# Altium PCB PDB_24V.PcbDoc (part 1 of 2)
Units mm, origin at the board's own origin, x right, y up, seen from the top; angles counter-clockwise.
Board outline 185 x 160 mm, 4 copper layers (Top Layer, Int1 (GND), Int2 (GND), Bottom Layer), stack 1.636 mm thick; 170 components, 90 nets, 598 pads, 1109 vias.
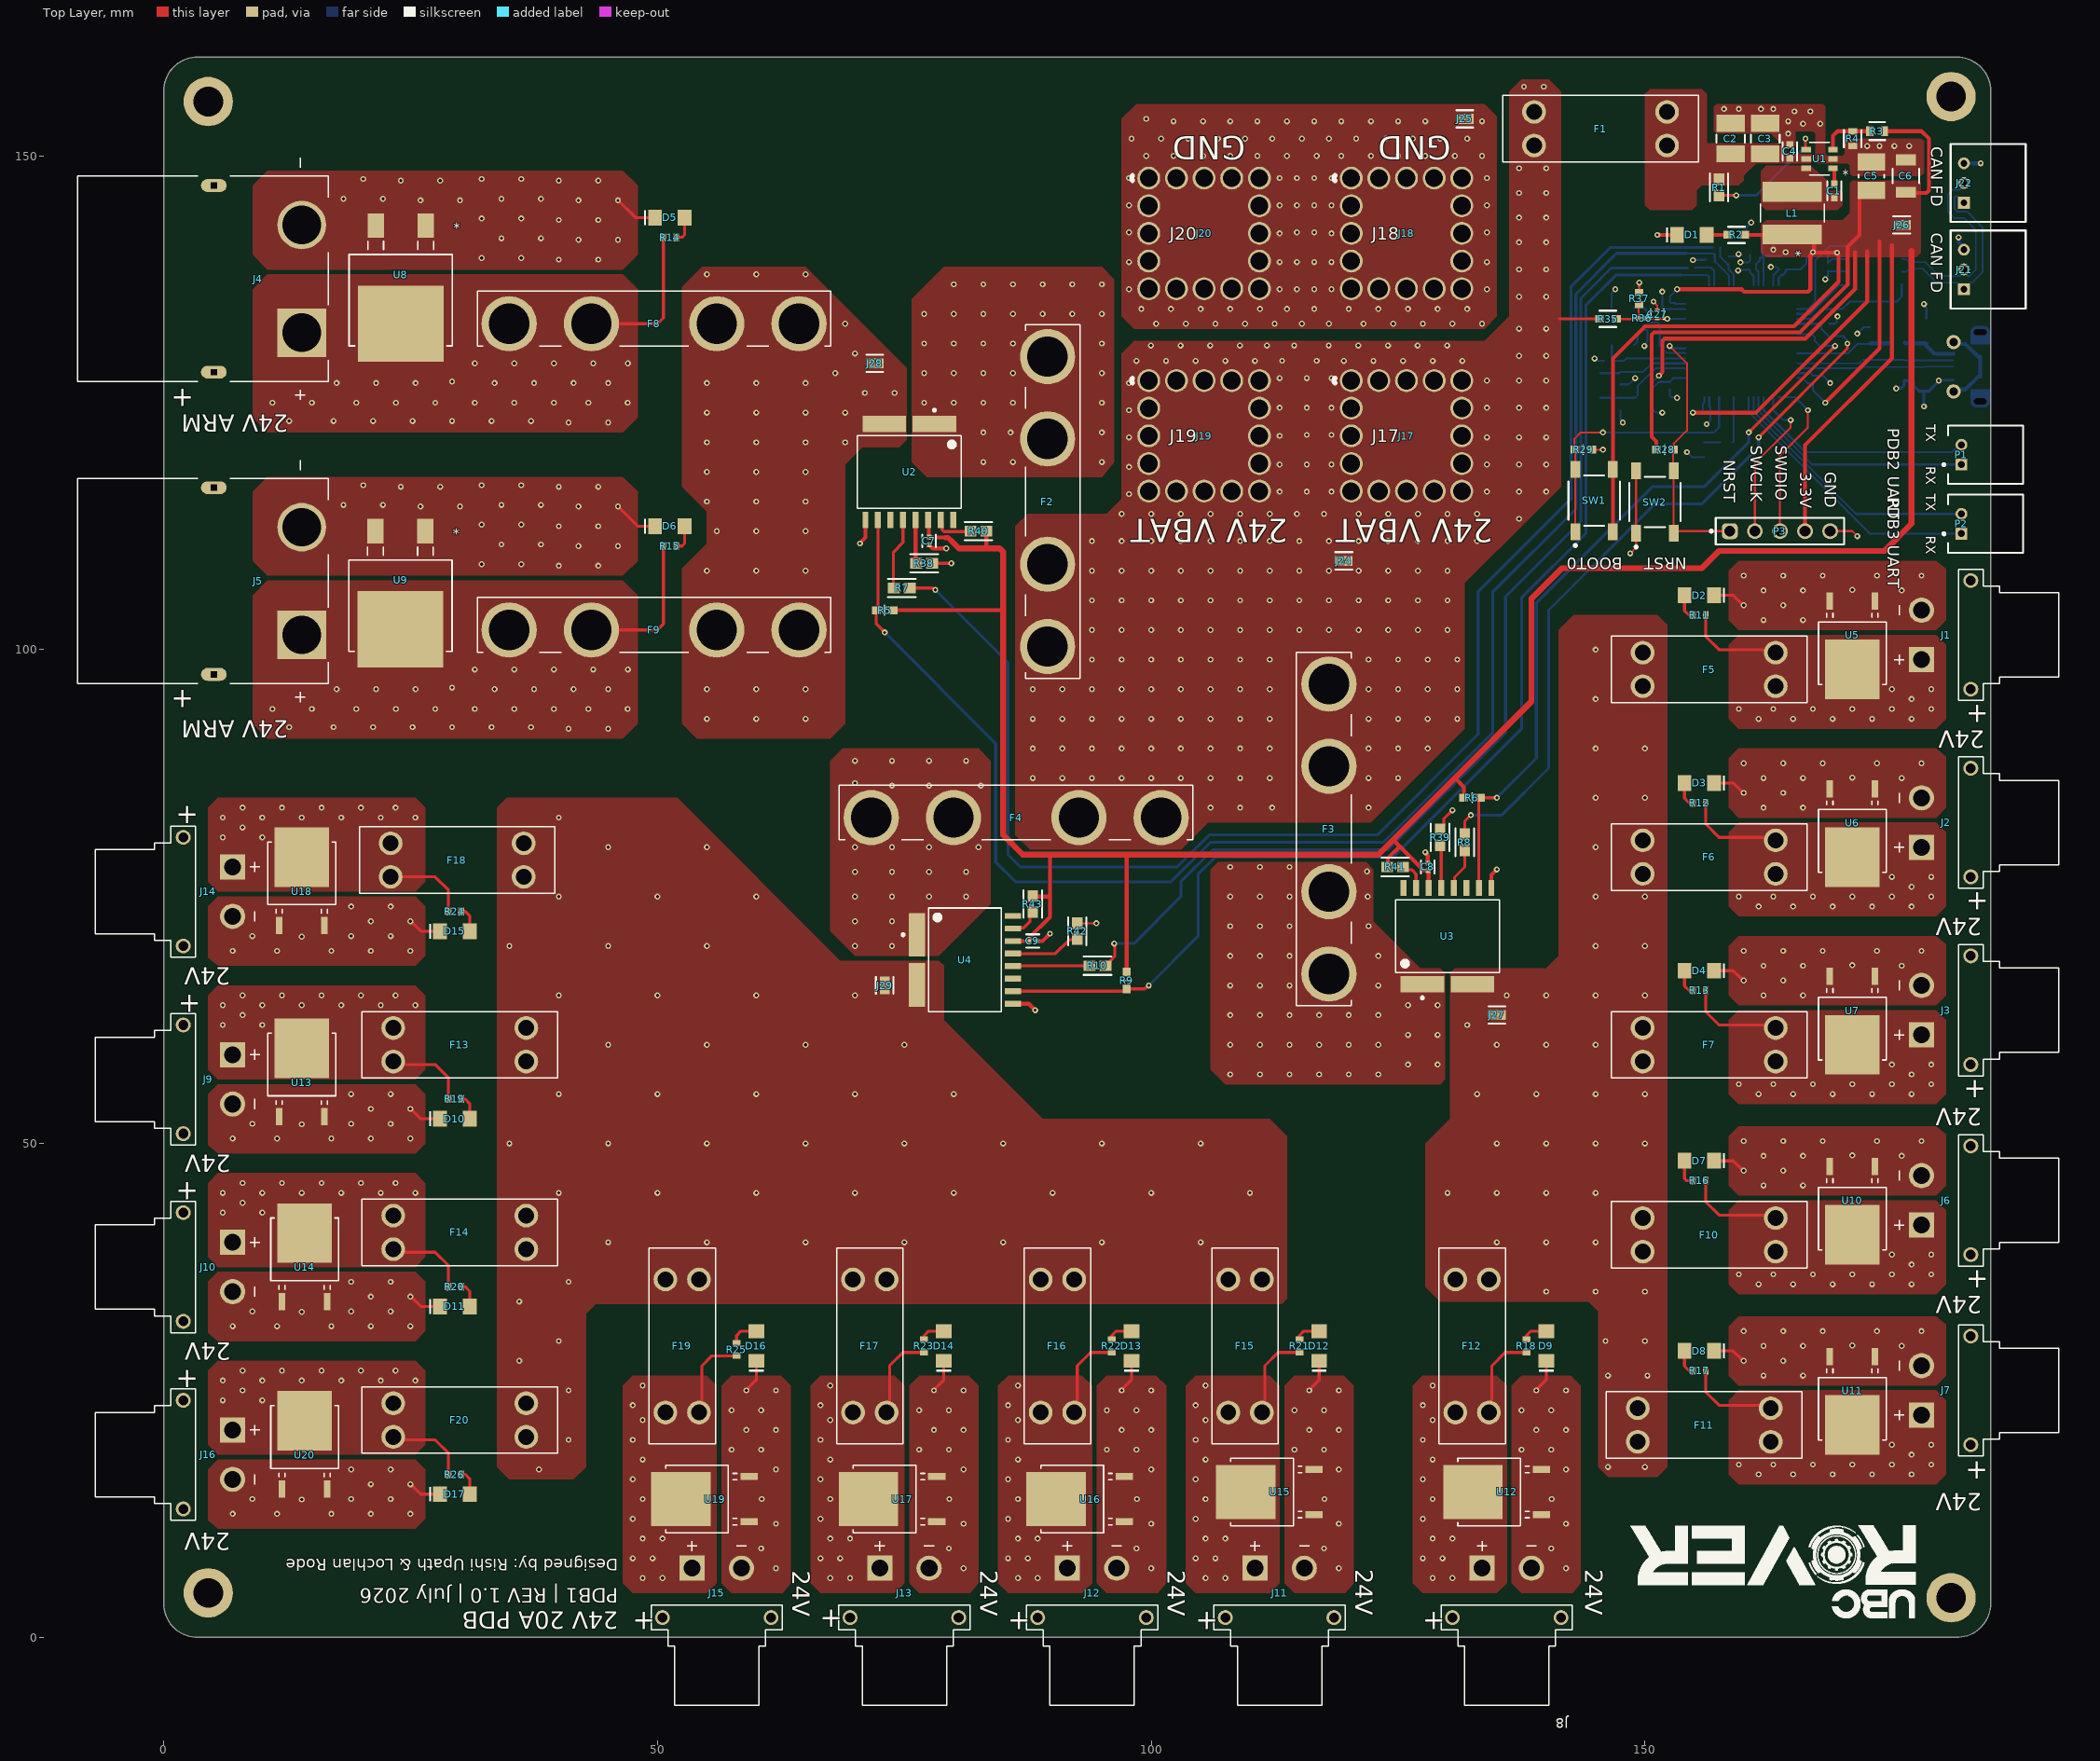
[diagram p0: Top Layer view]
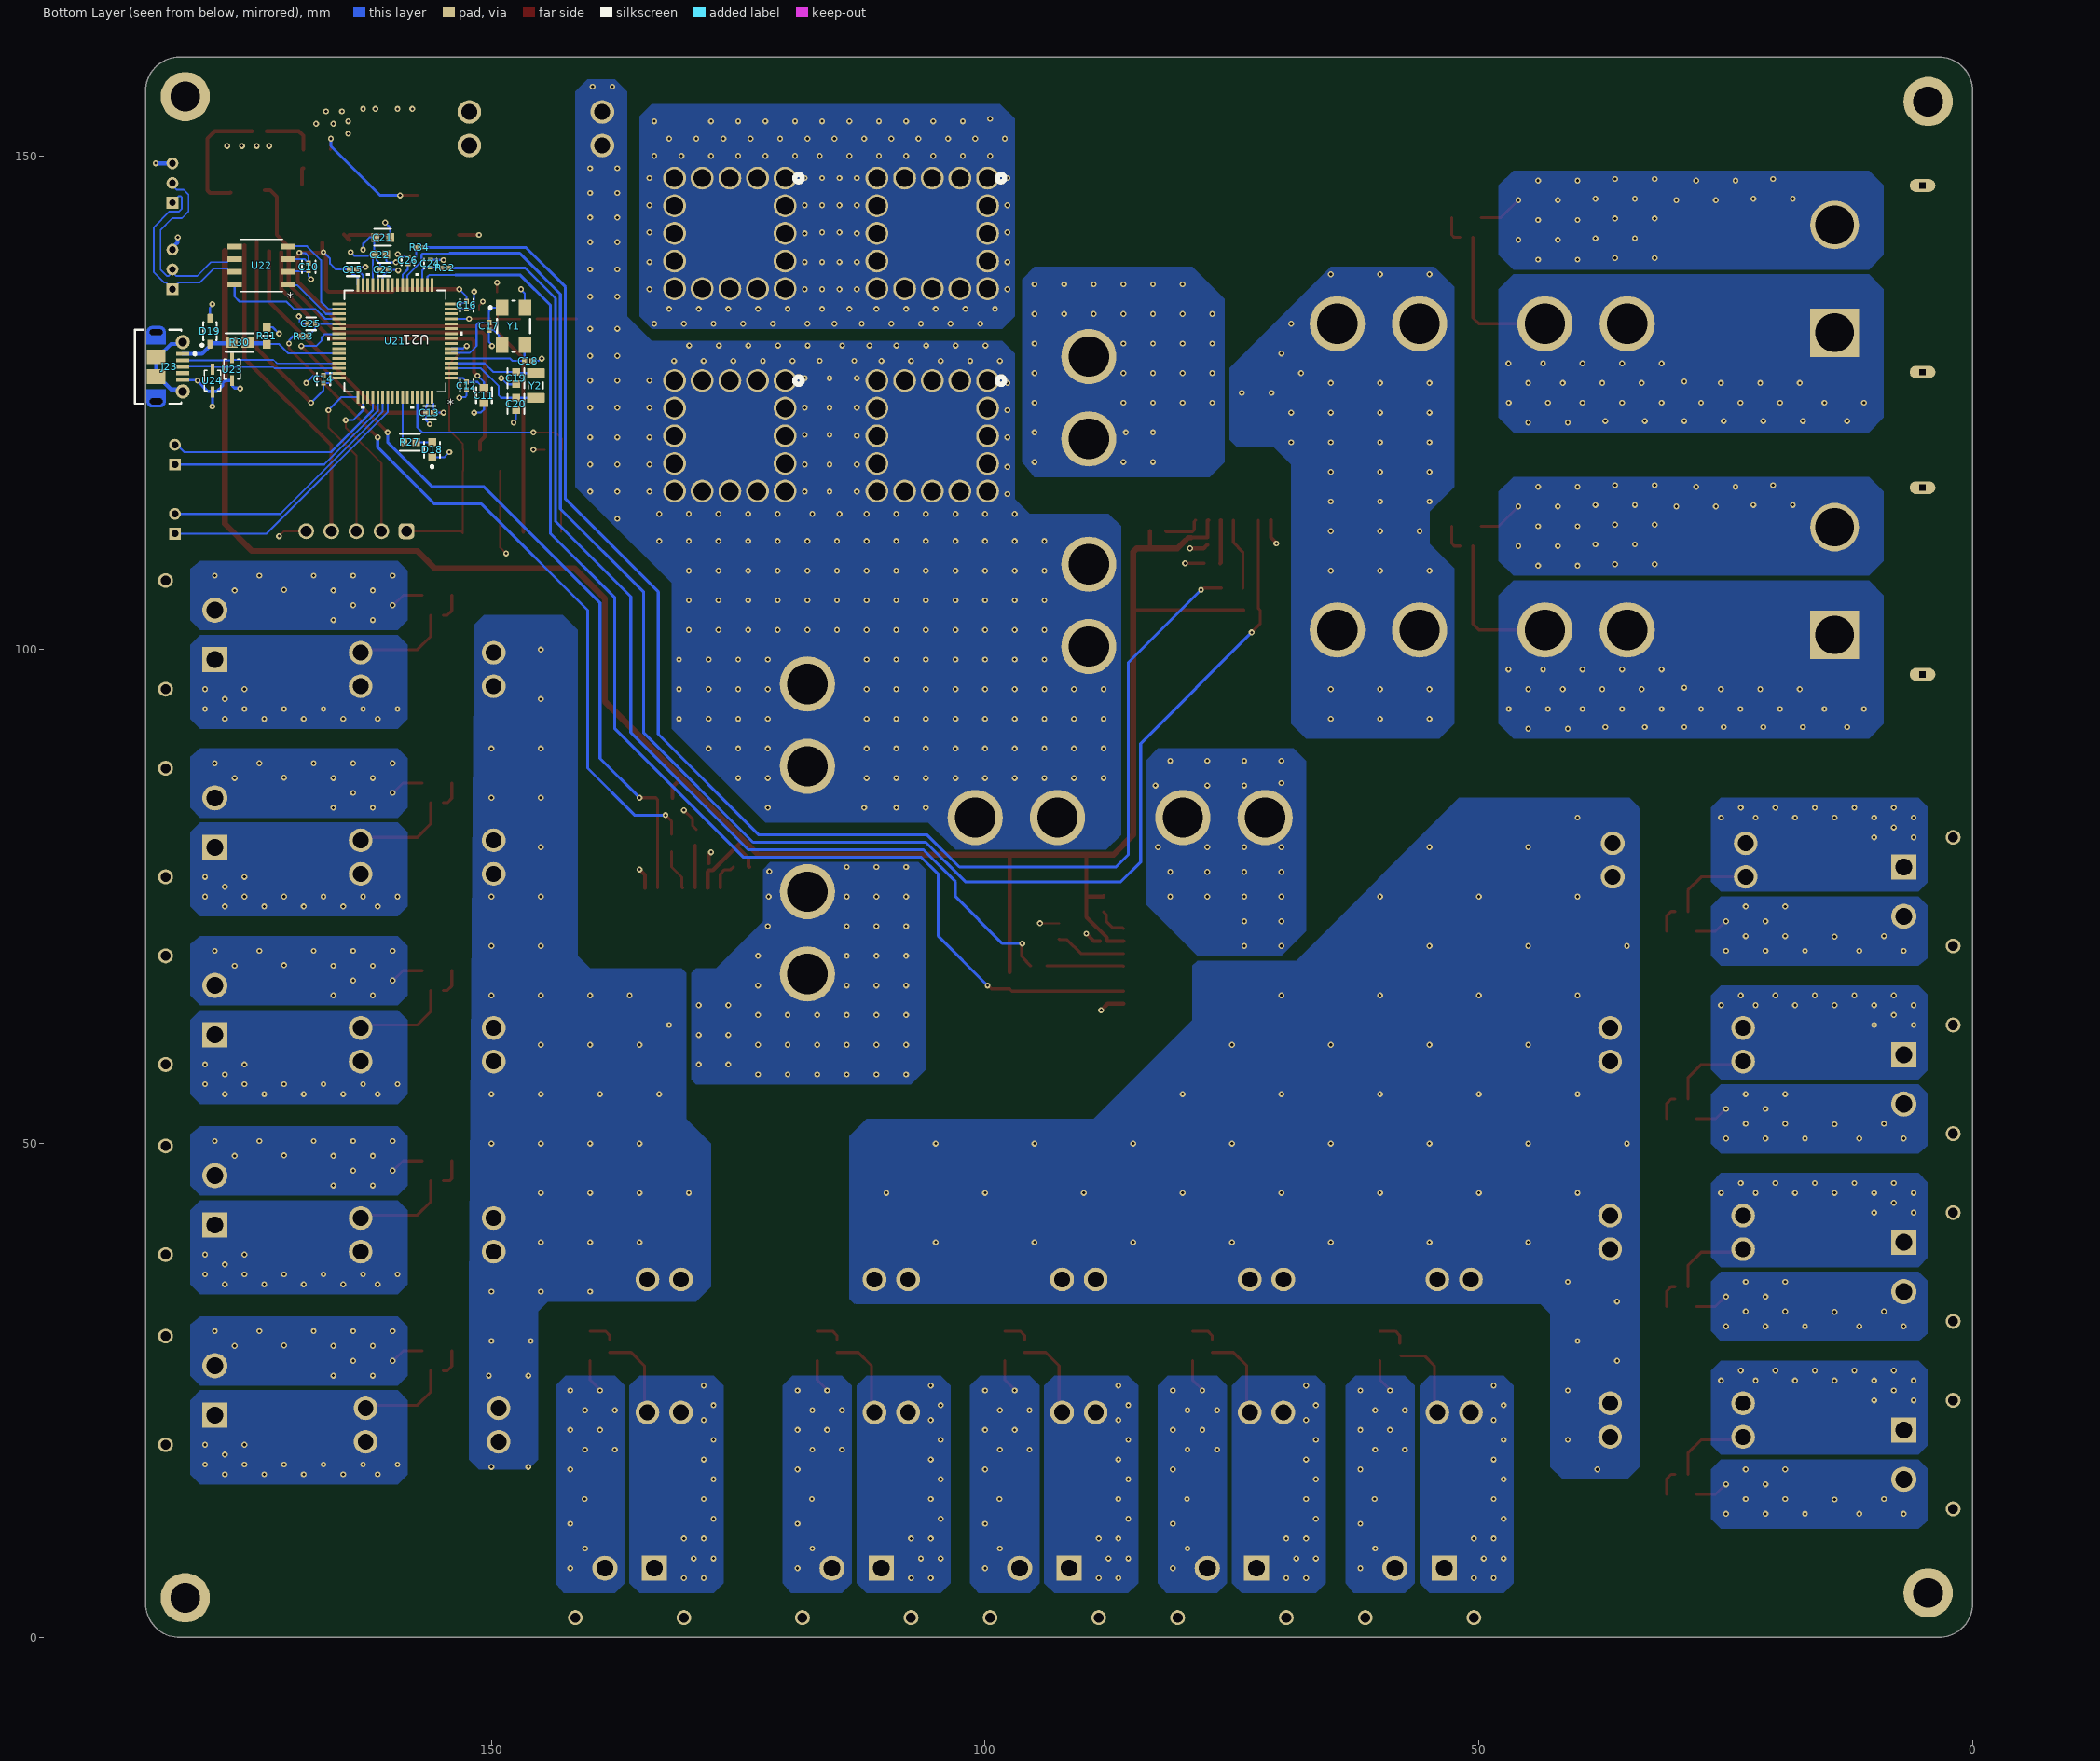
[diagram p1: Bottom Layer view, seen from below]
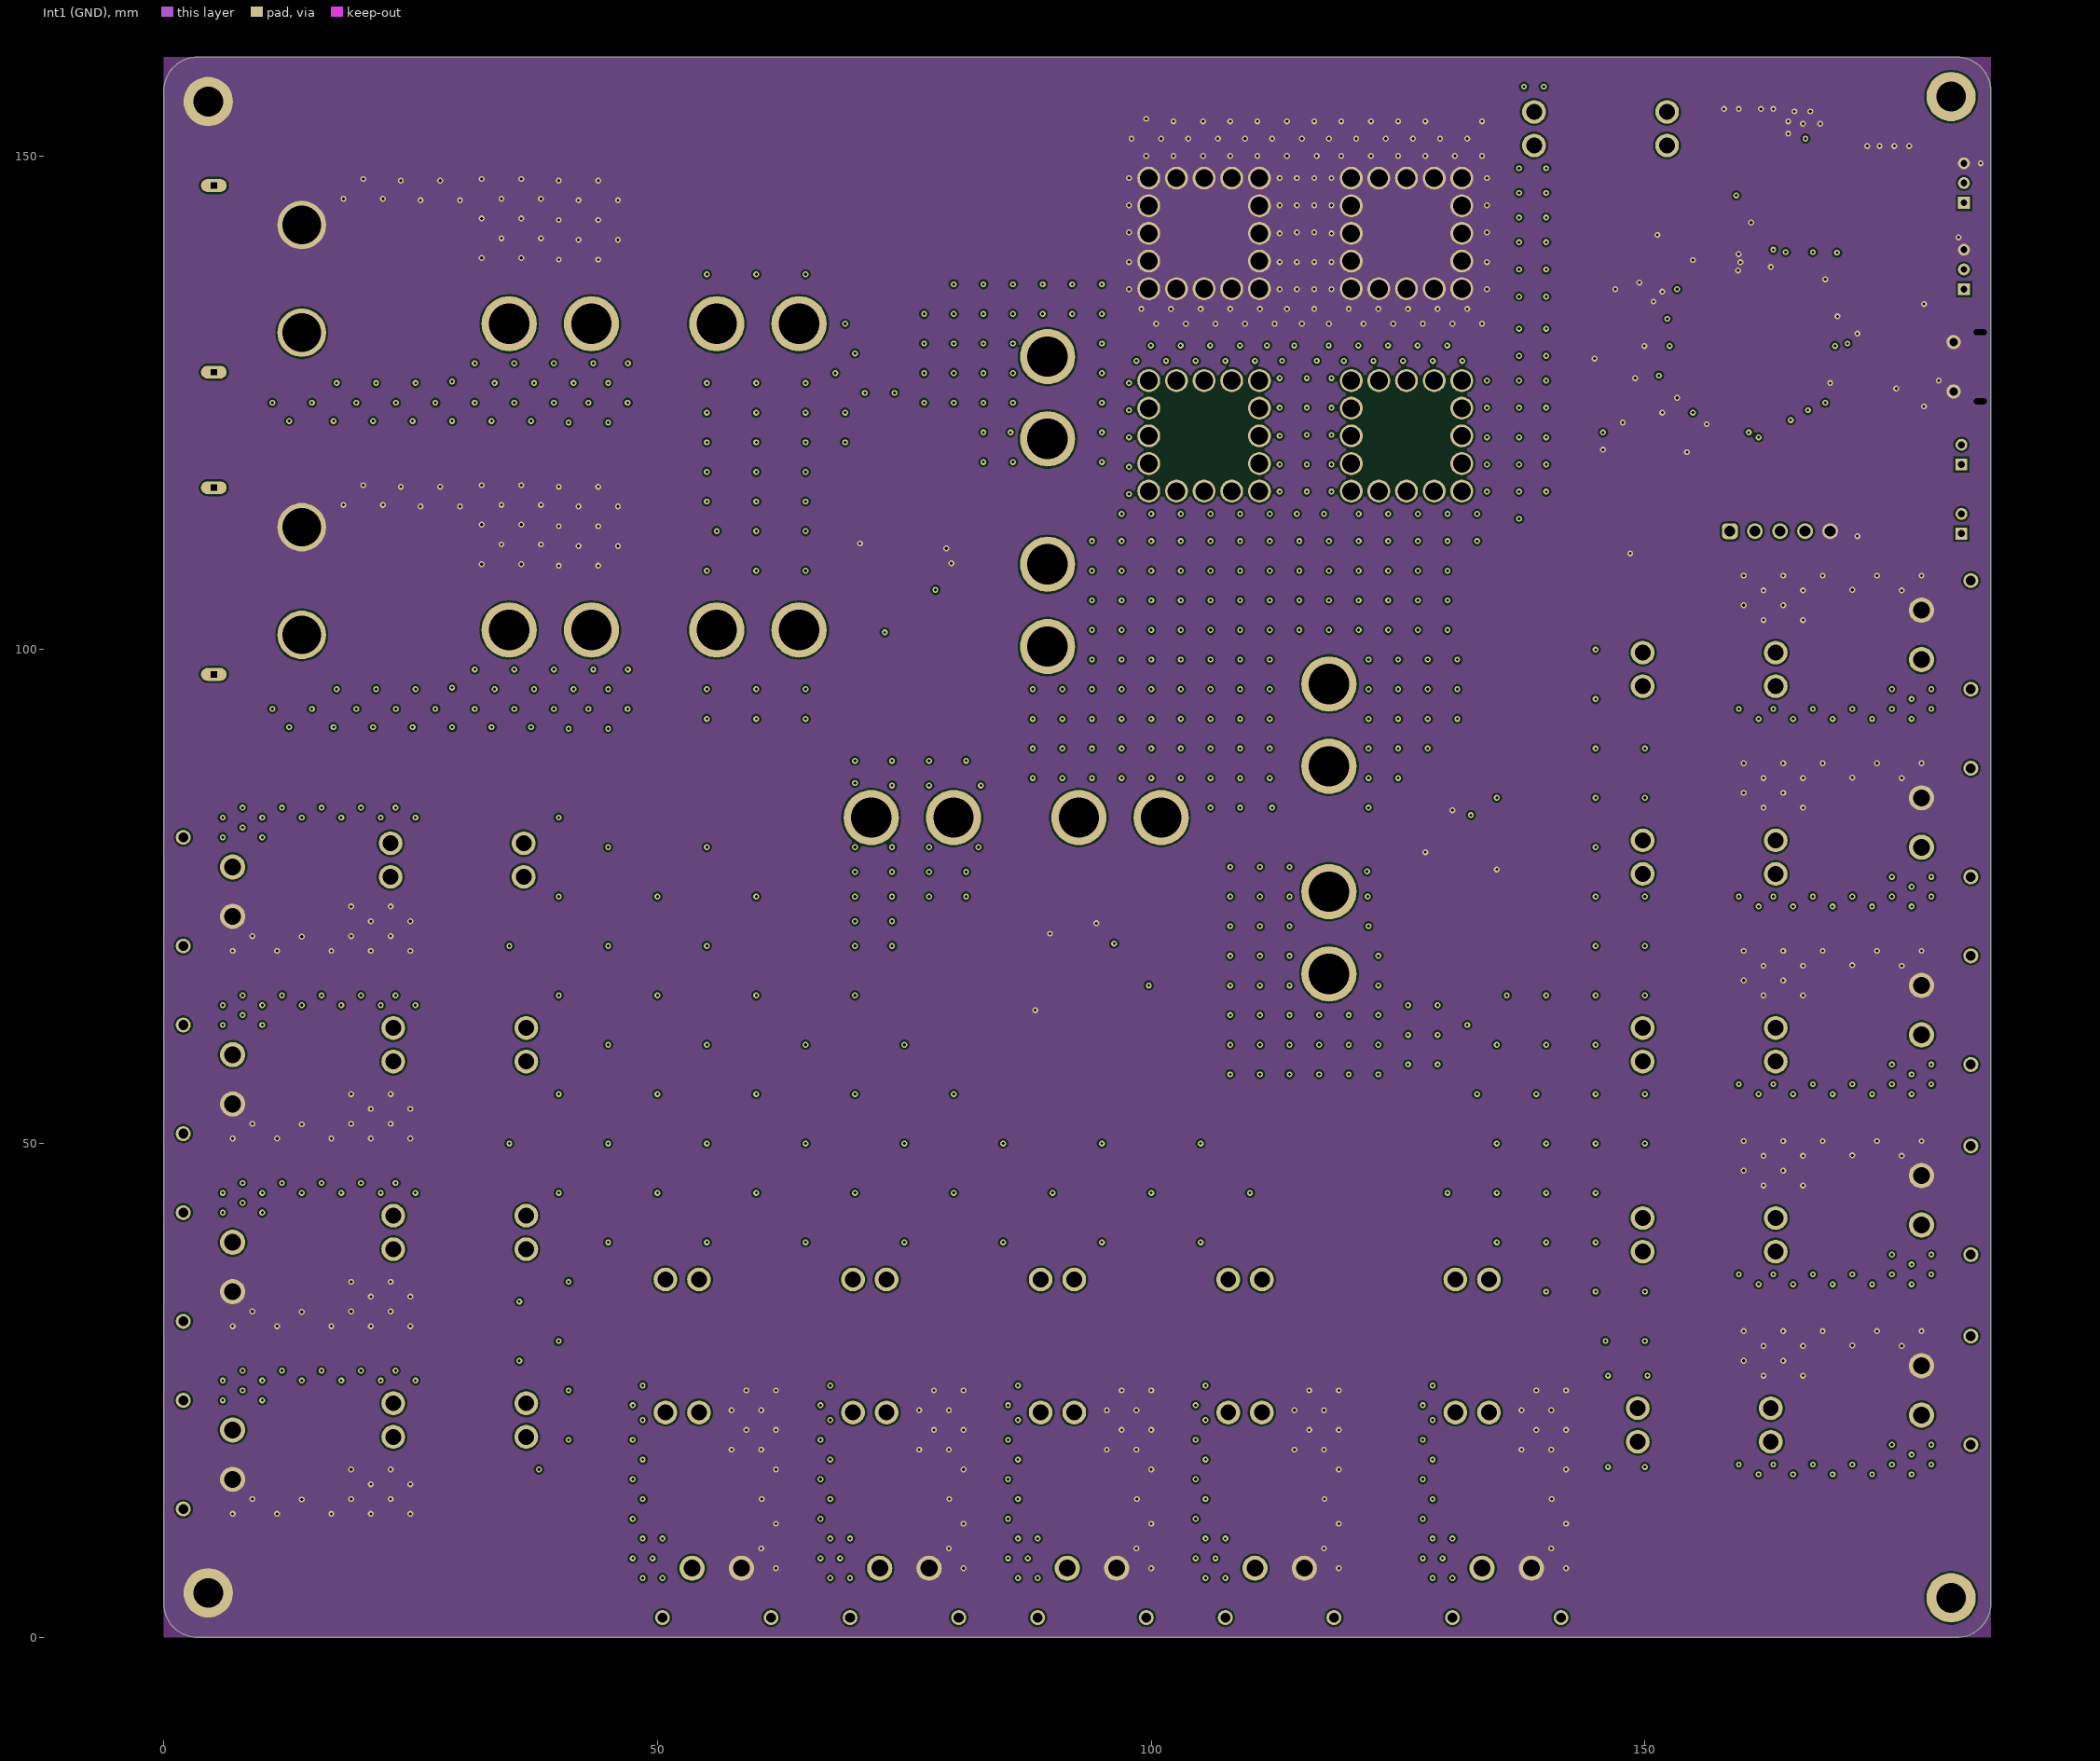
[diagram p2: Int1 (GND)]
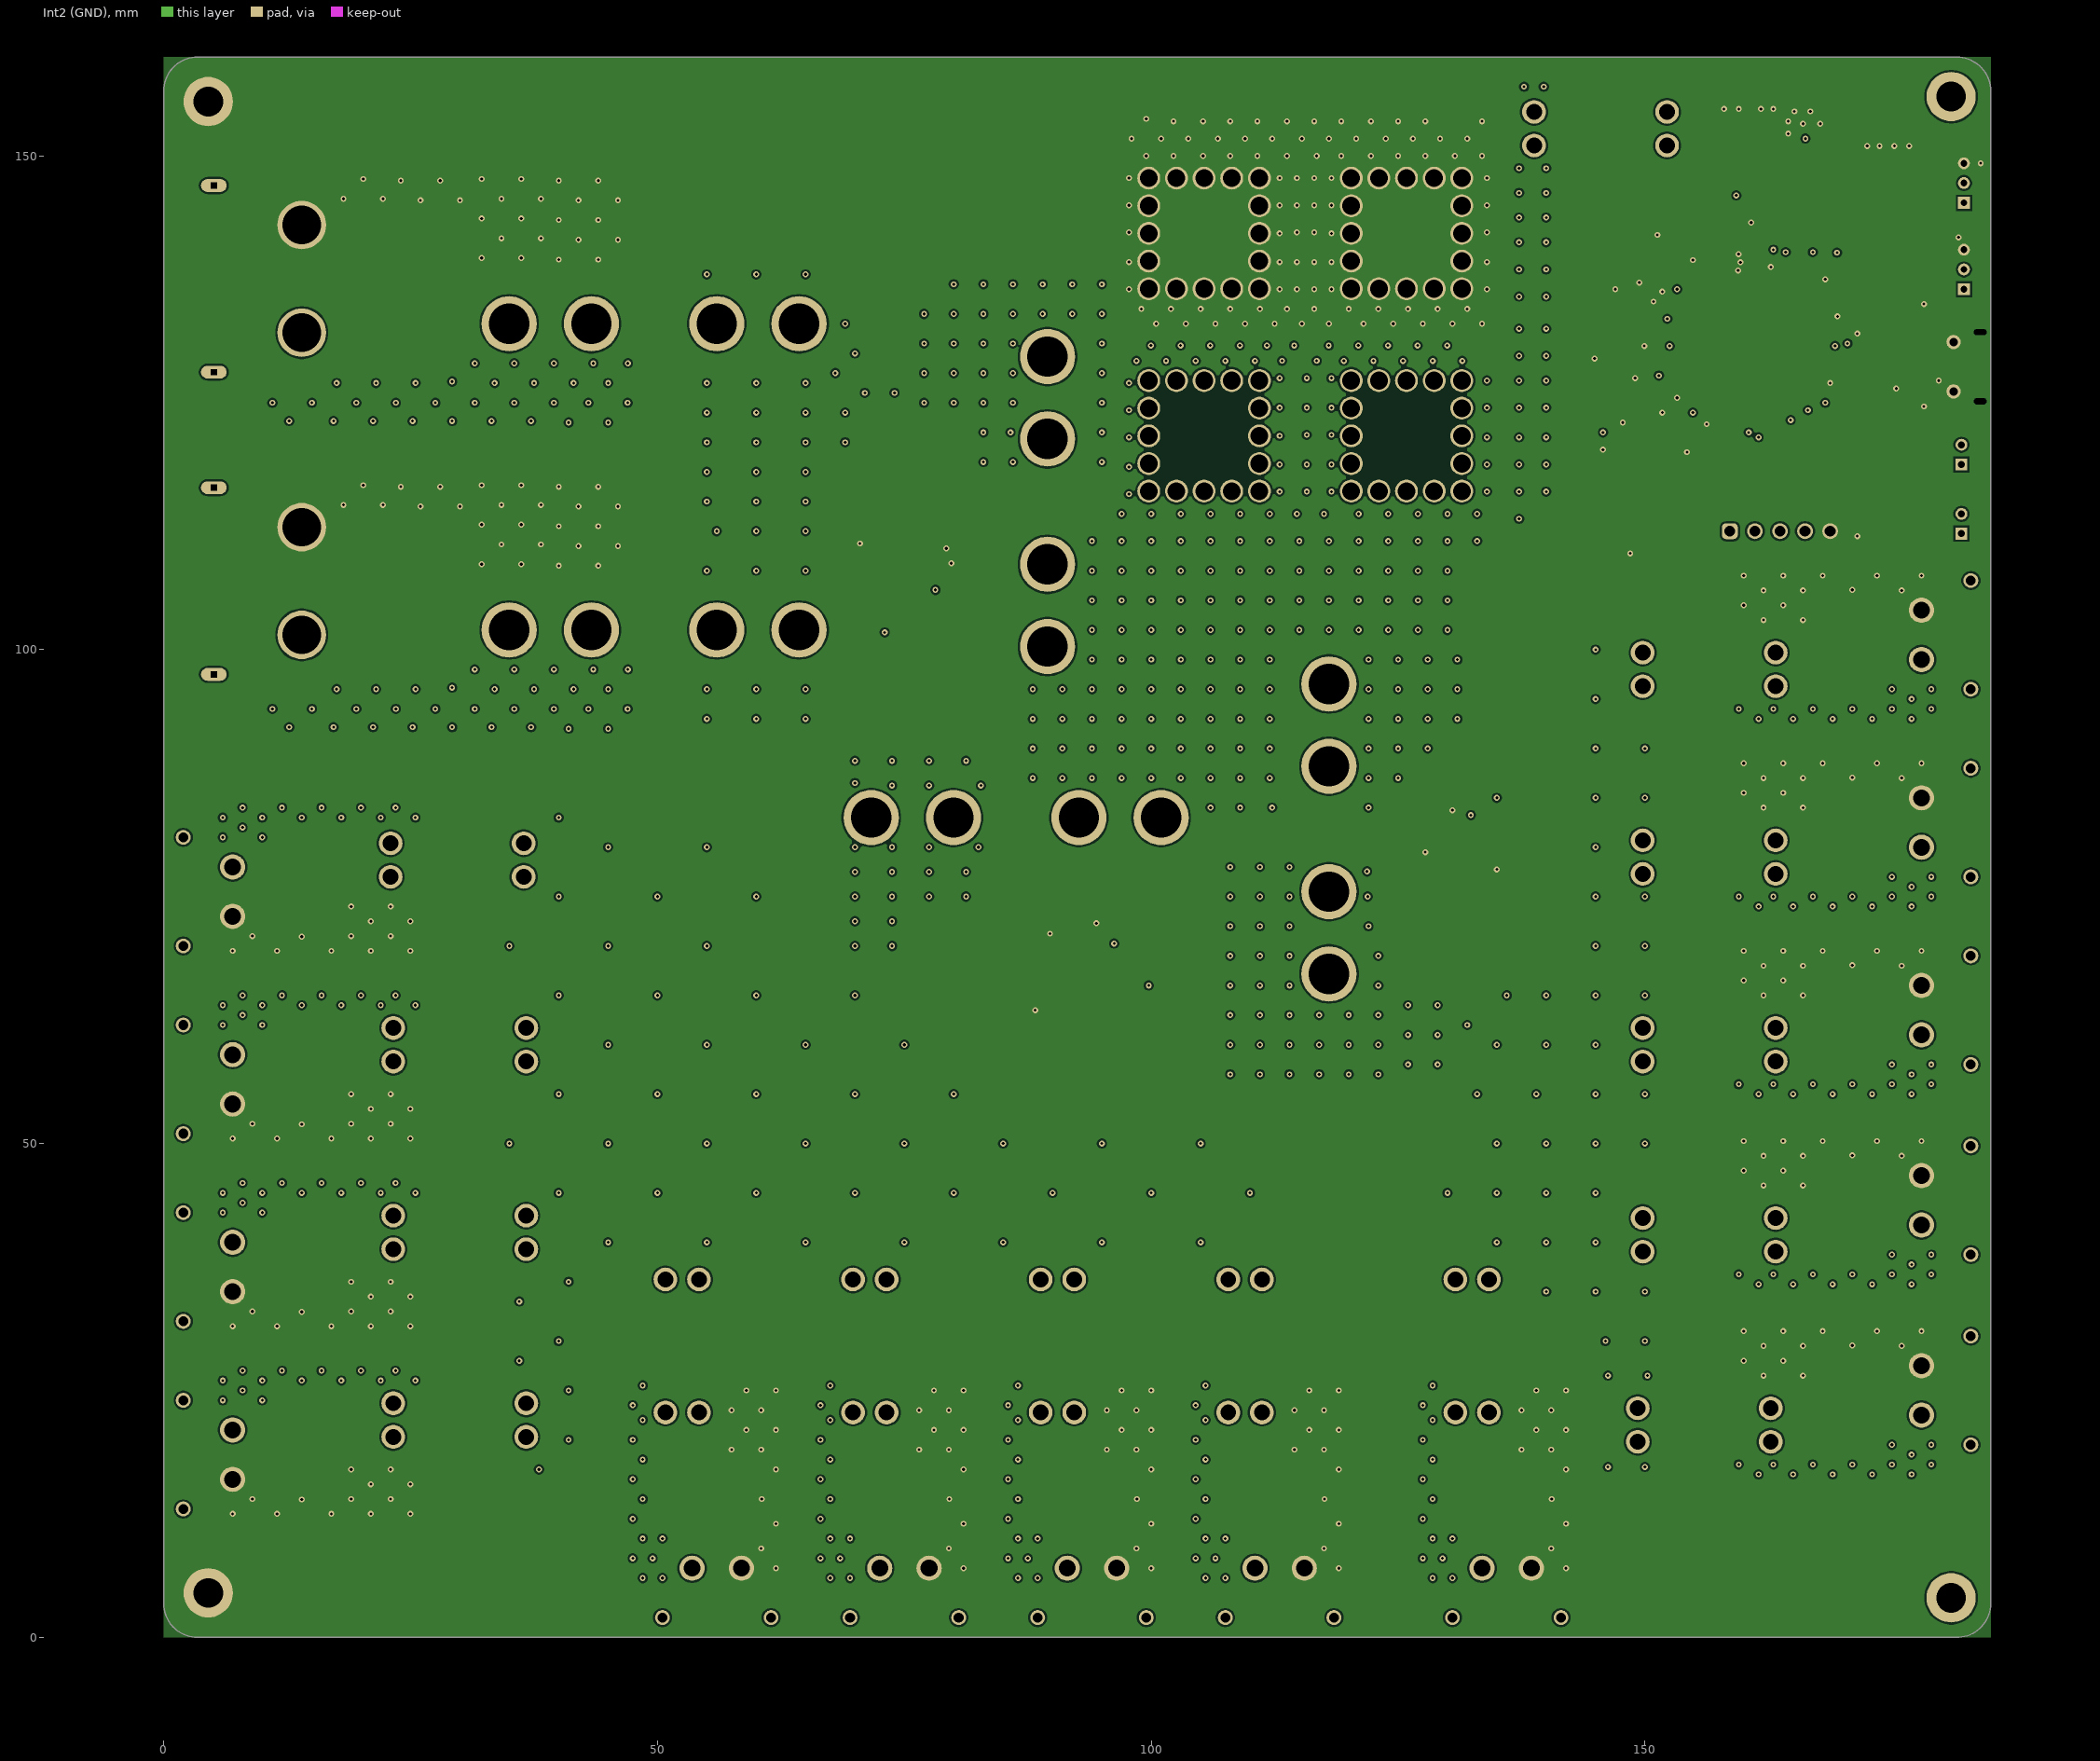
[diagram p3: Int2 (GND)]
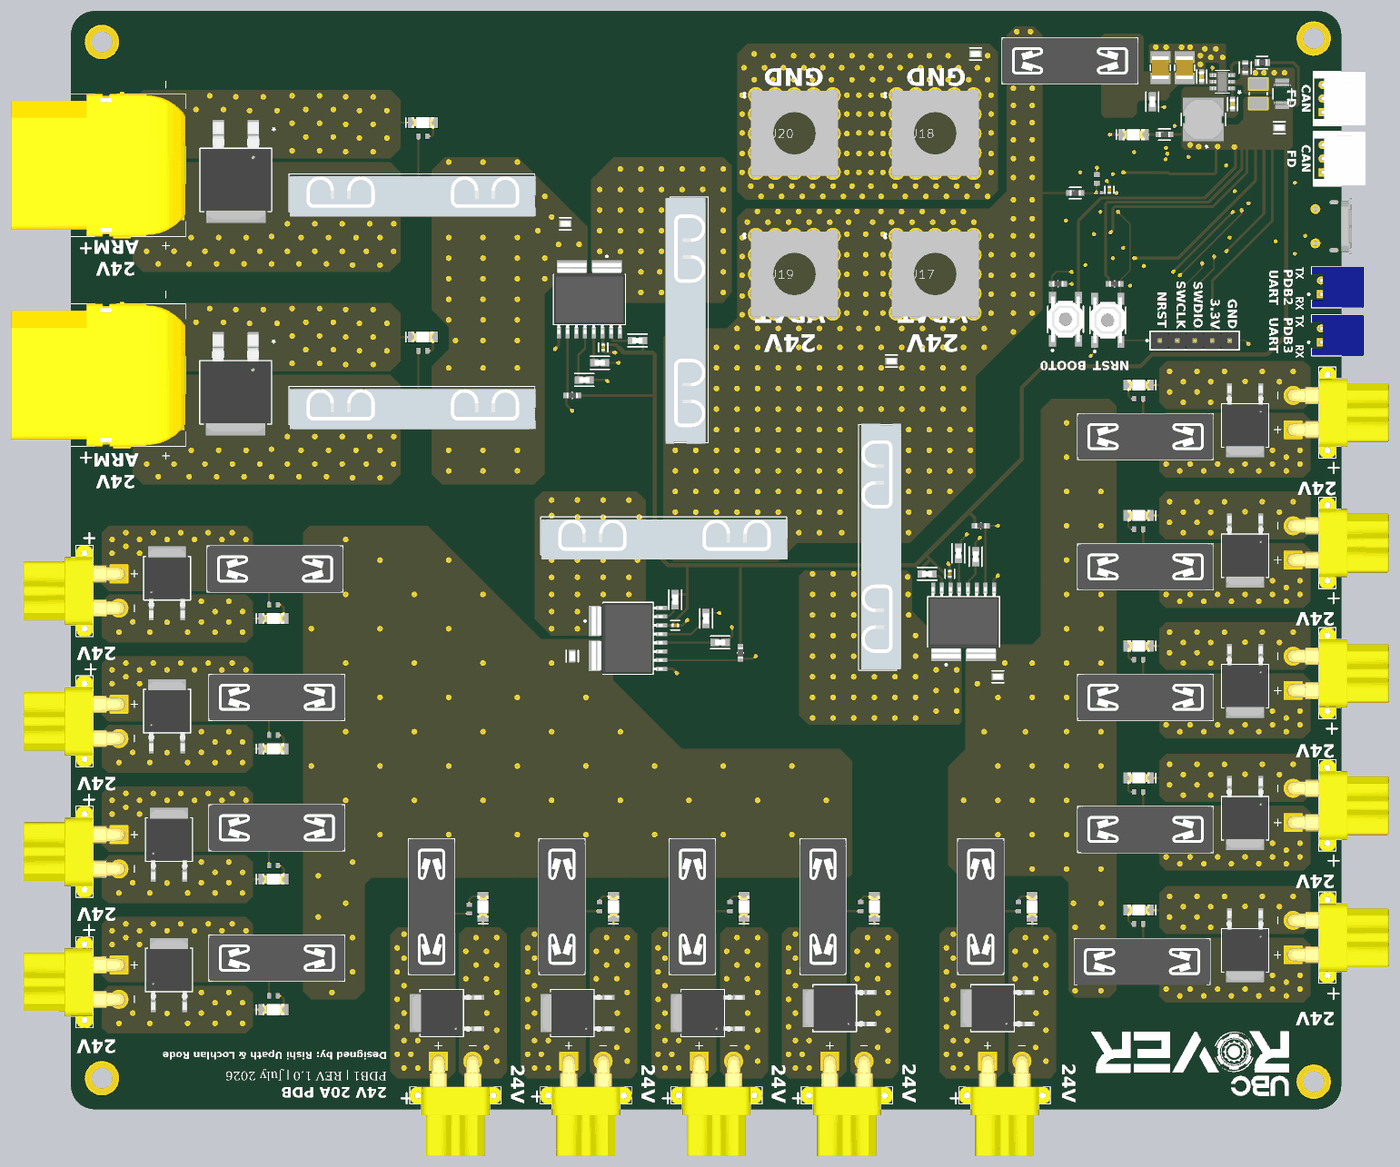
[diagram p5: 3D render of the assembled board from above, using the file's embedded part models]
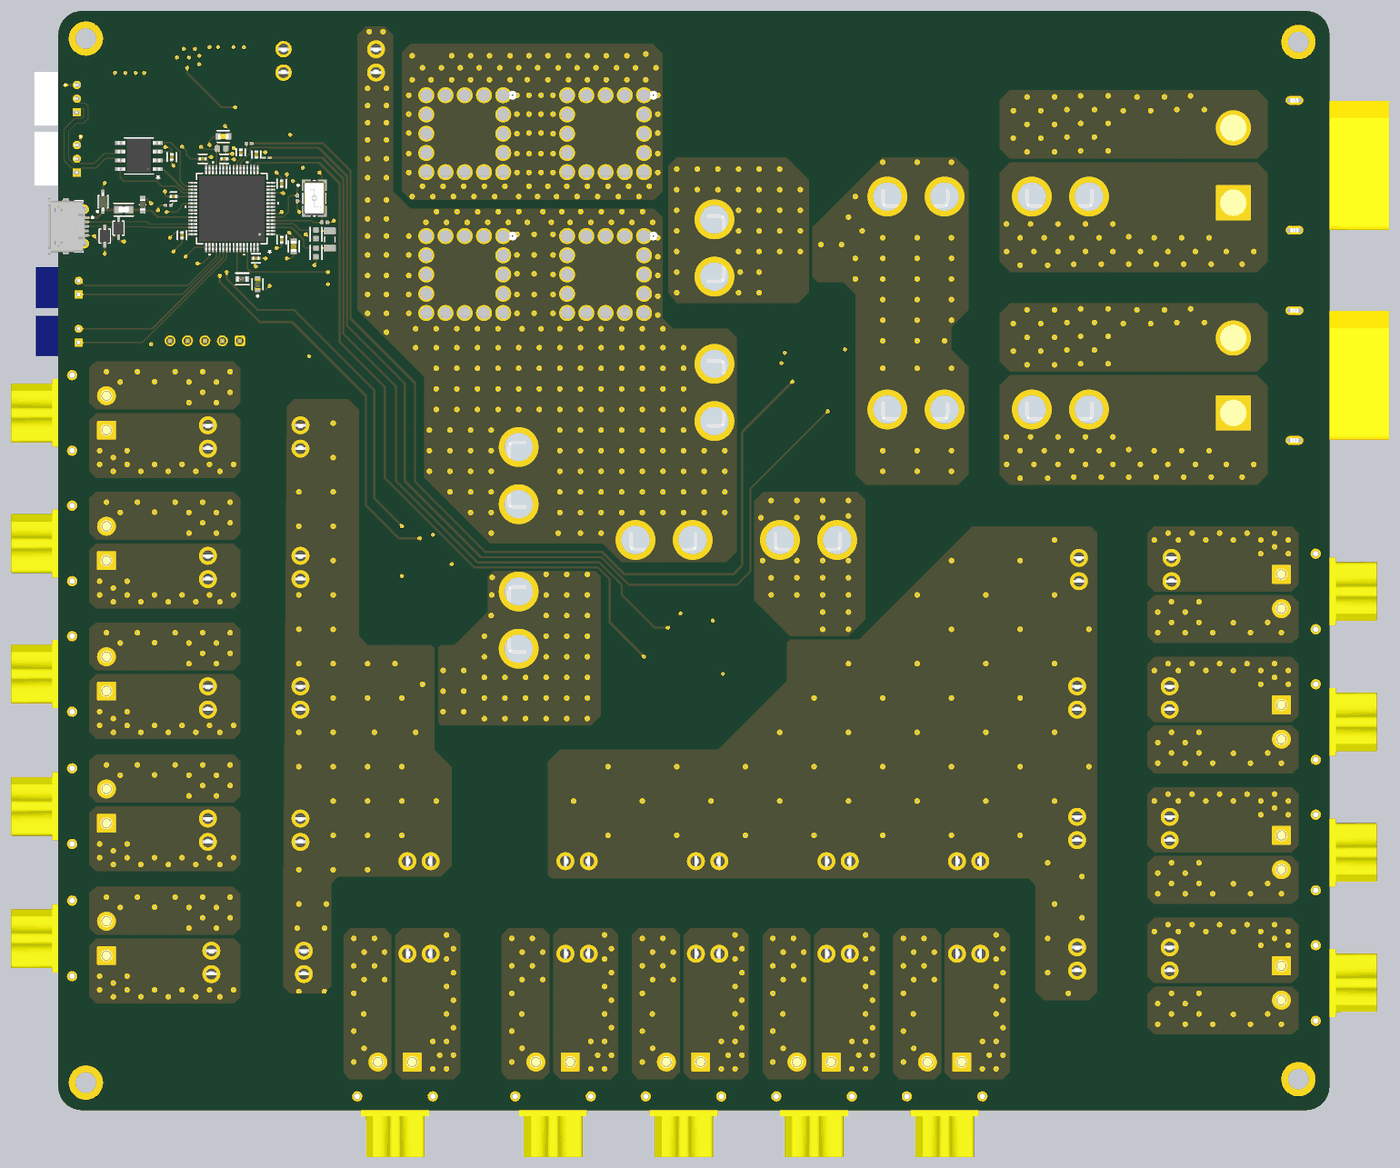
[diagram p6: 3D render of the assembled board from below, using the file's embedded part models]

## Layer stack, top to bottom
Top Solder: solder mask 0.0254, SM-001, Dk 4
Top Layer: signal copper 0.07
Dielectric 1: prepreg 0.203, PP-022, Dk 4.5
Int1 (GND): signal copper 0.03
Dielectric 3: core 1.03, Core-039, Dk 4.8
Int2 (GND): signal copper 0.03
Dielectric 5: prepreg 0.203, PP-022, Dk 4.5
Bottom Layer: signal copper 0.07
Bottom Solder: solder mask 0.0254, SM-001, Dk 4

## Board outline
3.414,0 cw(c3.414,3.414) 0,3.414 0,156.586 cw(c3.414,156.586) 3.414,160 181.586,160 cw(c181.586,156.586) 185,156.586 185,3.414 cw(c181.586,3.414) 181.519,0.001 cw(c181.519,0.001) 181.519,0

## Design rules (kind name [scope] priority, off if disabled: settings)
Clearance [All] p1: gap=0.2 ignorepadtopadclearanceinfootprint=FALSE
DiffPairsRouting DiffPairsRouting_CAN [InDifferentialPair('CAN')] p1: maxlimit=0.5 minlimit=0.203 mostfreqgap=0.5 toplayer_mingap=0.5 toplayer_minwidth=0.172 toplayer_maxwidth=0.172 toplayer_prefwidth=0.172 bottomlayer_mingap=0.5 bottomlayer_minwidth=0.172 bottomlayer_maxwidth=0.172 bottomlayer_prefwidth=0.172 impedanceprofiledriven=TRUE impedanceprofileid={7FC673FF-01E3-40F9-A78E-6FFD32FF9D5F} impedanceprofilevalue=120.000000 maxuncoupledlength=12.7
DiffPairsRouting DiffPairsRouting_USB [InDifferentialPair('USB_D')] p2: maxlimit=0.254 minlimit=0.127 mostfreqgap=0.254 toplayer_maxgap=0.127 toplayer_prefgap=0.127 toplayer_minwidth=0.148 toplayer_maxwidth=0.148 toplayer_prefwidth=0.148 bottomlayer_maxgap=0.127 bottomlayer_prefgap=0.127 bottomlayer_minwidth=0.148 bottomlayer_maxwidth=0.148 bottomlayer_prefwidth=0.148 impedanceprofiledriven=TRUE impedanceprofileid={548AC05E-11D8-4320-9B4C-721629B8BD8F} impedanceprofilevalue=90.000000 maxuncoupledlength=12.7
HoleSize [All] p1: absolutevalues=TRUE maxlimit=6.3 minlimit=0.025 maxpercent=80.000 minpercent=20.000
HoleToHoleClearance [All] p1: gap=0.2 allowstackedmicrovias=TRUE
PlaneConnect [All] p1: planeconnectstyle=Direct reliefexpansion=0.508 reliefentries=4 reliefconductorwidth=0.254 reliefairgap=0.254
PolygonConnect [All] p1: connectstyle=Direct reliefconductorwidth=0.254 reliefentries=4 polygonreliefangle="90 Angle" airgapwidth=0.254
RoutingVias [All] p1: holewidth=0.3 width=0.7 viastyle="Through Hole" minholewidth=0.25 minwidth=0.55 maxholewidth=0.4 maxwidth=0.9
SolderMaskExpansion [All] p1: expansion=0.102 istentingtop=FALSE
SupplyNets "Schematic Supply Nets_31" [InNet('24V_SPARE_1')] p1: voltage=0.000
SupplyNets "Schematic Supply Nets_30" [InNet('24V')] p2: voltage=0.000
SupplyNets "Schematic Supply Nets_29" [InNet('24V_SPARE_5')] p3: voltage=0.000
SupplyNets "Schematic Supply Nets_28" [InNet('24V_M5')] p4: voltage=0.000
SupplyNets "Schematic Supply Nets_27" [InNet('24V_ARM_S')] p5: voltage=0.000
SupplyNets "Schematic Supply Nets_26" [InNet('24V_ARM1')] p6: voltage=0.000
SupplyNets "Schematic Supply Nets_25" [InNet('24V_M4')] p7: voltage=0.000
SupplyNets "Schematic Supply Nets_24" [InNet('24V_CHASSIS_F')] p8: voltage=0.000
SupplyNets "Schematic Supply Nets_23" [InNet('24V_LIGTHING')] p9: voltage=0.000
SupplyNets "Schematic Supply Nets_22" [InNet('24V_M2')] p10: voltage=0.000
SupplyNets "Schematic Supply Nets_21" [InNet('24V_CHASSIS_S')] p11: voltage=0.000
SupplyNets "Schematic Supply Nets_20" [InNet('24V_ARM_F')] p12: voltage=0.000
SupplyNets "Schematic Supply Nets_19" [InNet('24V_SCIENCE')] p13: voltage=0.000
SupplyNets "Schematic Supply Nets_18" [InNet('24V_ARM2')] p14: voltage=0.000
SupplyNets "Schematic Supply Nets_16" [InNet('24V_M0')] p15: voltage=0.000
SupplyNets "Schematic Supply Nets_15" [InNet('24V_MISC_S')] p16: voltage=0.000
SupplyNets "Schematic Supply Nets_14" [InNet('24V_SPARE_3')] p17: voltage=0.000
SupplyNets "Schematic Supply Nets_13" [InNet('24V_BUCK')] p18: voltage=0.000
SupplyNets "Schematic Supply Nets_12" [InNet('24V_PoE')] p19: voltage=0.000
SupplyNets "Schematic Supply Nets_11" [InNet('24V_SPARE_2')] p20: voltage=0.000
SupplyNets "Schematic Supply Nets_10" [InNet('24V_M1')] p21: voltage=0.000
SupplyNets "Schematic Supply Nets_9" [InNet('24V_MISC_F')] p22: voltage=0.000
SupplyNets "Schematic Supply Nets_8" [InNet('24V_M3')] p23: voltage=0.000
SupplyNets "Schematic Supply Nets_7" [InNet('24V_SPARE_4')] p24: voltage=0.000
SupplyNets "Schematic Supply Nets_4" [InNet('3.3V')] p25: voltage=0.000
SupplyNets "Schematic Supply Nets_1" [InNet('GND')] p26: voltage=0.000
UnRoutedNet [All] p1: checkbadconnections=TRUE
Width Width_RF [InNet('RF')] p1: maxlimit=0.348 minlimit=0.254 preferedwidth=0.348 toplayer_minwidth=0.348 bottomlayer_minwidth=0.348 impedanceprofiledriven=TRUE minimp=50.000000 maximp=50.000000 favimp=50.000000
Width Width_All [All] p2: maxlimit=1 minlimit=0.09 preferedwidth=0.3 midlayer1_minwidth=0.254 midlayer1_maxwidth=0.254 midlayer1_prefwidth=0.254 midlayer2_minwidth=0.254 midlayer2_maxwidth=0.254 midlayer2_prefwidth=0.254 minimp=50.000000 maximp=50.000000 favimp=50.000000
25 further rules are at their usual default settings.

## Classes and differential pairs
net class USB: USB_D_P
component class PDB_24V_Power: C1 C2 C3 C4 C5 C6 C7 C8 C9 D1 F1 F2 F3 F4 J24 J25 J26 J27 J28 J29 L1 R1 R2 R3 R4 R5 R6 R7 R8 R9 R10 R38 R39 R40 R41 R42 R43 U1 U2 U3 U4
component class PDB_24V_MCU_Peripherals: C10 C11 C12 C13 C14 C15 C16 C17 C18 C19 C20 C21 C22 C23 C24 C25 C26 C27 D18 D19 J21 J22 J23 P1 P2 P3 R27 R28 R29 R30 R31 R32 R33 R34 R35 R36 R37 SW1 SW2 U21 U22 U23 U24 Y1 Y2
component class PDB_24V_Connectors: D2 D3 D4 D5 D6 D7 D8 D9 D10 D11 D12 D13 D14 D15 D16 D17 F5 F6 F7 F8 F9 F10 F11 F12 F13 F14 F15 F16 F17 F18 F19 F20 J1 J2 J3 J4 J5 J6 J7 J8 J9 J10 J11 J12 J13 J14 J15 J16 J17 J18 J19 J20 R11 R12 R13 R14 R15 R16 R17 R18 R19 R20 R21 R22 R23 R24 R25 R26 U5 U6 U7 U8 U9 U10 U11 U12 U13 U14 U15 U16 U17 U18 U19 U20
differential pair CAN: +CAN_P -CAN_N
differential pair USB_D: +USB_D_P -USB_D_N

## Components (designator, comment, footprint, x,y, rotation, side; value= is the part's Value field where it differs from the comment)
C1 "CGA3E3X8R1H104K080AB" FP-CGA3E-0_3-0_1-MFG 169.176,146.45 r270 top value=100nF
C2 "12105C475KAT2A" FP-1210-L_3_3_0_4-W_2_5_0-IPC_A 158.676,151.75 r90 top value=4.7uF
C3 "12105C475KAT2A" FP-1210-L_3_3_0_4-W_2_5_0-IPC_A 162.176,151.75 r90 top value=4.7uF
C4 "CGA3E3X8R1H104K080AB" FP-CGA3E-0_3-0_1-MFG 164.676,150.45 r270 top value=100nF
C5 "UMK325BJ106MM-T" TAYO-C1210-2_M 172.926,147.95 r270 top value=10µF
C6 "GRM32ER61E226KE15L" FP-GRM32-MFG 176.426,147.95 r270 top value=22µF
C7 "CL05B104KA5NNNC" FP-CL830-IPC_C 77.5,111 r90 top value=100nF
C8 "CL05B104KA5NNNC" FP-CL830-IPC_C 128,78 r270 top value=100nF
C9 "CL05B104KA5NNNC" FP-CL830-IPC_C 88,70.5 r180 top value=100nF
C10 "CL05B104KA5NNNC" FP-CL830-IPC_C 168.5,138.75 r90 bottom value=100nF
C11 "GRM188R61E475KE11D" FP-GRM188-0_15-MFG 150.75,125.75 r90 bottom value=4.7µF
C12 "CL05B104KA5NNNC" FP-CL830-IPC_C 152.5,126.727 r90 bottom value=100nF
C13 "CL05B104KA5NNNC" FP-CL830-IPC_C 156.25,124 r180 bottom value=100nF
C14 "CL05B104KA5NNNC" FP-CL830-IPC_C 167,127.379 r270 bottom value=100nF
C15 "CL05B104KA5NNNC" FP-CL830-IPC_C 164,138.5 r0 bottom value=100nF
C16 "CL05B104KA5NNNC" FP-CL830-IPC_C 152.5,134.871 r90 bottom value=100nF
C17 "GRM1555C1H180JA01D" CAPC1005X55X25LL05T10 150.25,132.75 r90 bottom value=18pF
C18 "GRM1555C1H180JA01D" CAPC1005X55X25LL05T10 146.25,129.25 r0 bottom value=18pF
C19 "CL10C060DB8NNNC" FP-CL10-IPC_C 147.5,127.5 r90 bottom value=6pF
C20 "CL10C060DB8NNNC" FP-CL10-IPC_C 147.5,124.873 r90 bottom value=6pF
C21 "CC0603KRX7R7BB105" FP-CC0603-DA-MFG 161,141.75 r0 bottom value=1µF
C22 "GCM188R71H103KA37D" CAPC1608X90X35LL10T15 161.25,140 r0 bottom value=10nF
C23 "CL05B104KA5NNNC" FP-CL830-IPC_C 160.871,138.5 r0 bottom value=100nF
C24 "GRM1555C1H102JA01D" FP-GRM155-0_05-MFG 156.175,139.1 r270 bottom value=1nF
C25 "GRM1555C1H102JA01D" FP-GRM155-0_05-MFG 168.25,133 r180 bottom value=1nF
C26 "GRM1555C1H102JA01D" FP-GRM155-0_05-MFG 158.45,139.425 r270 bottom value=1nF
C27 "GRM1555C1H102JA01D" FP-GRM155-0_05-MFG 151.243,133.95 r270 top value=1nF
D1 "150120VS75000" WL-SMCW_1206_150120xx75000 154.75,142 r0 top
D2 "150120VS75000" WL-SMCW_1206_150120xx75000 155.5,105.5 r180 top
D3 "150120VS75000" WL-SMCW_1206_150120xx75000 155.5,86.5 r180 top
D4 "150120VS75000" WL-SMCW_1206_150120xx75000 155.5,67.5 r180 top
D5 "150120VS75000" WL-SMCW_1206_150120xx75000 51.25,143.75 r0 top
D6 "150120VS75000" WL-SMCW_1206_150120xx75000 51.25,112.5 r0 top
D7 "150120VS75000" WL-SMCW_1206_150120xx75000 155.5,48.25 r180 top
D8 "150120VS75000" WL-SMCW_1206_150120xx75000 155.5,29 r180 top
D9 "150120VS75000" WL-SMCW_1206_150120xx75000 140,29.5 r90 top
D10 "150120VS75000" WL-SMCW_1206_150120xx75000 29.475,52.5 r0 top
D11 "150120VS75000" WL-SMCW_1206_150120xx75000 29.475,33.5 r0 top
D12 "150120VS75000" WL-SMCW_1206_150120xx75000 117,29.5 r90 top
D13 "150120VS75000" WL-SMCW_1206_150120xx75000 98,29.5 r90 top
D14 "150120VS75000" WL-SMCW_1206_150120xx75000 79,29.5 r90 top
D15 "150120VS75000" WL-SMCW_1206_150120xx75000 29.475,71.5 r0 top
D16 "150120VS75000" WL-SMCW_1206_150120xx75000 60,29.5 r90 top
D17 "150120VS75000" WL-SMCW_1206_150120xx75000 29.475,14.5 r0 top
D18 "LTST-C191KGKT" FP-LTST-C191KGKT-MFG 156,120.25 r90 bottom
D19 "TSD05DYFR" FP-DYF0002A-MFG 178.5,132.25 r90 bottom
F1 "3557-2" FUSE_3557-2 145.5,152.75 r0 top
F2 "3555-2" FUSE_3555-2 89.5,115 r90 top
F3 "3555-2" FUSE_3555-2 118,81.845 r270 top
F4 "3555-2" FUSE_3555-2 86.315,83 r180 top
F5 "3557-2" FUSE_3557-2 156.5,98 r0 top
F6 "3557-2" FUSE_3557-2 156.5,79 r0 top
F7 "3557-2" FUSE_3557-2 156.5,60 r0 top
F8 "3555-2" FUSE_3555-2 49.65,133 r180 top
F9 "3555-2" FUSE_3555-2 49.65,102 r180 top
F10 "3557-2" FUSE_3557-2 156.5,40.75 r0 top
F11 "3557-2" FUSE_3557-2 156,21.5 r0 top
F12 "3557-2" FUSE_3557-2 132.5,29.5 r270 top
F13 "3557-2" FUSE_3557-2 29.975,60 r180 top
F14 "3557-2" FUSE_3557-2 29.975,41 r180 top
F15 "3557-2" FUSE_3557-2 109.5,29.5 r270 top
F16 "3557-2" FUSE_3557-2 90.5,29.5 r270 top
F17 "3557-2" FUSE_3557-2 71.5,29.5 r270 top
F18 "3557-2" FUSE_3557-2 29.71,78.7 r180 top
F19 "3557-2" FUSE_3557-2 52.5,29.5 r270 top
F20 "3557-2" FUSE_3557-2 29.975,22 r180 top
J1 "XT30PW-F" AMASS_XT30PW-F 183,101.5 r270 top
J2 "XT30PW-F" AMASS_XT30PW-F 183,82.5 r270 top
J3 "XT30PW-F" AMASS_XT30PW-F 183,63.5 r270 top
J4 "XT90PW-F" AMASS_XT90PW-F 5.075,137.55 r270 top
J5 "XT90PW-F" AMASS_XT90PW-F 5.075,106.95 r270 top
J6 "XT30PW-F" AMASS_XT30PW-F 183,44.25 r270 top
J7 "XT30PW-F" AMASS_XT30PW-F 183,25 r270 top
J8 "XT30PW-F" AMASS_XT30PW-F 136,2 r180 top
J9 "XT30PW-F" AMASS_XT30PW-F 1.975,56.5 r90 top
J10 "XT30PW-F" AMASS_XT30PW-F 1.975,37.5 r90 top
J11 "XT30PW-F" AMASS_XT30PW-F 113,2 r180 top
J12 "XT30PW-F" AMASS_XT30PW-F 94,2 r180 top
J13 "XT30PW-F" AMASS_XT30PW-F 75,2 r180 top
J14 "XT30PW-F" AMASS_XT30PW-F 1.975,75.5 r90 top
J15 "XT30PW-F" AMASS_XT30PW-F 56,2 r180 top
J16 "XT30PW-F" AMASS_XT30PW-F 1.975,18.5 r90 top
J17 "S93515" CONN16_S93515_WRE 120.25,127.25 r0 top
J18 "S93515" CONN16_S93515_WRE 120.25,147.75 r0 top
J19 "S93515" CONN16_S93515_WRE 99.75,127.25 r0 top
J20 "S93515" CONN16_S93515_WRE 99.75,147.75 r0 top
J21 "S3B-PH-K-S(LF)(SN)" FP-S3B-PH-K-S_LF_SN-MFG 184.75,138.5 r270 top
J22 "S3B-PH-K-S(LF)(SN)" FP-S3B-PH-K-S_LF_SN-MFG 184.75,147.25 r270 top
J23 "1050170001" USB-MICRO-B_V 182.6,128.65 r270 bottom
J24 "S2761-46R" FP-S2761-46R-MFG 119.5,109 r180 top
J25 "S2761-46R" FP-S2761-46R-MFG 131.75,153.75 r180 top
J26 "S2761-46R" FP-S2761-46R-MFG 176,143 r180 top
J27 "S2761-46R" FP-S2761-46R-MFG 135,63 r180 top
J28 "S2761-46R" FP-S2761-46R-MFG 72,129 r180 top
J29 "S2761-46R" FP-S2761-46R-MFG 73,66 r90 top
L1 "SRN6045-8R2Y" IND_BOURNS_SRN6045 164.926,144.2 r90 top value=8.2uH
P1 "S2B-PH-K-S(LF)(SN)" JST-S2B-PH-K-S_V 184.5,119.75 r90 top
P2 "S2B-PH-K-S(LF)(SN)" JST-S2B-PH-K-S_V 184.5,112.75 r90 top
P3 "61300511121" 61300511121 163.67,112 r0 top
R1 "RMCF0603ZT0R00" FP-RMCF0603-IPC_A 157.5,146.801 r270 top value=0
R2 "AC0603FR-07130RL" FP-AC0603-MFG 159.25,142 r180 top value=130
R3 "CRCW060369K8FKEB" FP-CRCW0603-e3-MFG 173.5,152.5 r0 top value=69.8k
R4 "RMCF0603FT22K1" FP-RMCF0603-MFG 171.026,151.75 r270 top value=22k1
R5 "RC0603FR-0710KL" FP-RC0603-0_55-MFG 73,104 r0 top value=10k
R6 "RC0603FR-0710KL" FP-RC0603-0_55-MFG 132.5,85 r180 top value=10k
R7 "RMCF0603ZT0R00" FP-RMCF0603-IPC_A 74.75,106.25 r0 top value=0
R8 "RMCF0603ZT0R00" FP-RMCF0603-IPC_A 131.75,80.5 r90 top value=0
R9 "RC0603FR-0710KL" FP-RC0603-0_55-MFG 97.5,66.5 r90 top value=10k
R10 "RMCF0603ZT0R00" FP-RMCF0603-IPC_A 94.551,68 r0 top value=0
R11 "RC0603FR-072K2L" RESC1608X55X25LL10T15 155.5,103.5 r0 top value=2.2k
R12 "RC0603FR-072K2L" RESC1608X55X25LL10T15 155.5,84.5 r0 top value=2.2k
R13 "RC0603FR-072K2L" RESC1608X55X25LL10T15 155.5,65.5 r0 top value=2.2k
R14 "RC0603FR-072K2L" RESC1608X55X25LL10T15 51.25,141.75 r180 top value=2.2k
R15 "RC0603FR-072K2L" RESC1608X55X25LL10T15 51.25,110.5 r180 top value=2.2k
R16 "RC0603FR-072K2L" RESC1608X55X25LL10T15 155.5,46.25 r0 top value=2.2k
R17 "RC0603FR-072K2L" RESC1608X55X25LL10T15 155.5,27 r0 top value=2.2k
R18 "RC0603FR-072K2L" RESC1608X55X25LL10T15 138,29.5 r270 top value=2.2k
R19 "RC0603FR-072K2L" RESC1608X55X25LL10T15 29.475,54.5 r180 top value=2.2k
R20 "RC0603FR-072K2L" RESC1608X55X25LL10T15 29.475,35.5 r180 top value=2.2k
R21 "RC0603FR-072K2L" RESC1608X55X25LL10T15 115,29.5 r270 top value=2.2k
R22 "RC0603FR-072K2L" RESC1608X55X25LL10T15 96,29.5 r270 top value=2.2k
R23 "RC0603FR-072K2L" RESC1608X55X25LL10T15 77,29.5 r270 top value=2.2k
R24 "RC0603FR-072K2L" RESC1608X55X25LL10T15 29.475,73.5 r180 top value=2.2k
R25 "RC0603FR-072K2L" RESC1608X55X25LL10T15 58,29.15 r270 top value=2.2k
R26 "RC0603FR-072K2L" RESC1608X55X25LL10T15 29.475,16.5 r180 top value=2.2k
R27 "CRGCQ0603J220R" FP-CRGCQ0603-IPC_C 158.25,121 r0 bottom value=220
R28 "RC0603FR-0710KL" FP-RC0603-0_55-MFG 152,120.25 r180 top value=10k
R29 "RC0603FR-0710KL" FP-RC0603-0_55-MFG 143.75,120.25 r180 top value=10k
R30 "RMCF0603ZT0R00" FP-RMCF0603-IPC_A 175.5,131.1 r0 bottom value=0
R31 "RC0603FR-0710KL" FP-RC0603-0_55-MFG 172.75,131.8 r270 bottom value=10k
R32 "RC0402FR-07150RL" RESC1005X40X25LL05T10 154.675,138.65 r0 bottom value=150
R33 "RC0402FR-07150RL" RESC1005X40X25LL05T10 169,131.75 r180 bottom value=150
R34 "RC0402FR-07150RL" RESC1005X40X25LL05T10 157.275,140.725 r0 bottom value=150
R35 "AC0603FR-0718KL" FP-AC0603-MFG 146.25,133.5 r180 top value=18k
R36 "RC0402FR-07150RL" RESC1005X40X25LL05T10 149.725,133.55 r0 top value=150
R37 "ERJ-3EKF2001V" RESC1608X55X30LL15T15 149.425,135.55 r270 top value=2k
R38 "RMCF0603ZT0R00" FP-RMCF0603-IPC_A 77,108.75 r0 top value=0
R39 "RMCF0603ZT0R00" FP-RMCF0603-IPC_A 129.25,81 r90 top value=0
R40 "RMCF0603ZT0R00" FP-RMCF0603-IPC_A 82.5,112 r180 top value=0
R41 "RMCF0603ZT0R00" FP-RMCF0603-IPC_A 124.699,78 r0 top value=0
R42 "RMCF0603ZT0R00" FP-RMCF0603-IPC_A 92.5,71.5 r90 top value=0
R43 "RMCF0603ZT0R00" FP-RMCF0603-IPC_A 88,74.25 r270 top value=0
SW1 "8-1437565-1" FP-8-1437565-1-MFG 144.85,115.1 r90 top
SW2 "8-1437565-1" FP-8-1437565-1-MFG 151,114.95 r90 top
U1 "LMR54410DBVR" SOT-23-6-DBV_TEX 167.676,149.7 r180 top
U2 "TMCS1123B1AQDVGR" DVG0010A-MFG 75.5,118 r270 top
U3 "TMCS1123B1AQDVGR" DVG0010A-MFG 130,71 r90 top
U4 "TMCS1123B1AQDVGR" DVG0010A-MFG 81.125,68.595 r0 top
U5 "SDT30B100D1-13" TO252_DIO 171,99.638 r180 top
U6 "SDT30B100D1-13" TO252_DIO 171,80.638 r180 top
U7 "SDT30B100D1-13" TO252_DIO 171,61.638 r180 top
U8 "V40DL45-M3I" SOT_45-M3I_VIS 24,135.388 r180 top
U9 "V40DL45-M3I" SOT_45-M3I_VIS 23.96,104.443 r180 top
U10 "SDT30B100D1-13" TO252_DIO 171,42.388 r180 top
U11 "SDT30B100D1-13" TO252_DIO 171,23.138 r180 top
U12 "SDT30B100D1-13" TO252_DIO 134.219,14.714 r90 top
U13 "SDT30B100D1-13" TO252_DIO 13.975,58 r0 top
U14 "SDT30B100D1-13" TO252_DIO 14.261,39.281 r0 top
U15 "SDT30B100D1-13" TO252_DIO 111.219,14.714 r90 top
U16 "SDT30B100D1-13" TO252_DIO 92,14 r90 top
U17 "SDT30B100D1-13" TO252_DIO 73,14 r90 top
U18 "SDT30B100D1-13" TO252_DIO 13.975,77.362 r0 top
U19 "SDT30B100D1-13" TO252_DIO 54,14 r90 top
U20 "SDT30B100D1-13" TO252_DIO 14.261,20.281 r0 top
U21 "STM32G491RET6" LQFP64_10X10_STM 159.75,131.25 r0 bottom
U22 "TCAN3404DRQ1" SOIC8_D_TEX 173.276,138.905 r0 bottom
U23 "D5V0L1B2WS-7" SOD323_DIO 176.25,128.4 r270 bottom
U24 "D5V0L1B2WS-7" SOD323_DIO 178.25,127.25 r270 bottom
Y1 "ABM3C-16.000MHZ-D4Y-T" FP-ABM3C-MFG 147.75,132.75 r270 bottom
Y2 "ABS07-166-32.768KHZ-T" EPSON-FC-135_V 145.5,126.75 r270 bottom

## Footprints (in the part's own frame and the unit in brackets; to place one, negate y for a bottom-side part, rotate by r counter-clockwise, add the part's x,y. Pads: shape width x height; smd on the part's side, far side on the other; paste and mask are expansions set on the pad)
61300511121 [mm] "Pin Header, pitch 2.54 mm, THT, Vertical, single row, 5p"
  rrect50% 1.6x1.6 hole 1.1: 1(-5.08,0)
  round 1.6 hole 1.1: 2(-2.54,0) 3(0,0) 4(2.54,0) 5(5.08,0)
  silkscreen extent -7.07,-1.35 6.5,1.35, body extent -6.35,-1.27 6.35,1.27, height 8.57
AMASS_XT30PW-F [mm]
  round 2.55 hole 1.7: N(-2.5,-5)
  rect 2.55x2.55 / inner round 2.55 / far side rect 2.55x2.55 hole 1.7: P(2.5,-5)
  round 1.508 hole 1: S1(5.5,0) S2(-5.5,0)
  silkscreen extent -6.65,-7.75 6.65,8.9, body extent -6.65,-6 6.65,8.9, height 5
AMASS_XT90PW-F [mm]
  round 4.916 hole 3.9: N(-5.45,8.9)
  rect 4.916x4.916 / inner round 4.916 / far side rect 4.916x4.916 hole 3.9: P(5.45,8.9)
  oval 1.3x2.6 hole 0.6 square: S1(9.45,0) S2(-9.45,0)
  silkscreen extent -12.25,-13.8 12.25,11.6, body extent -10.65,-13.8 10.65,11.6, height 10.3
CAPC1005X55X25LL05T10 [mm] "Chip Capacitor, 2-Leads, Body 1.00x0.50mm, IPC High Density"
  rect 0.56x0.52 smd: 1(-0.39,0) 2(0.39,0)
  body extent -0.53,-0.28 0.53,0.28, height 0.55
CAPC1608X90X35LL10T15 [mm] "Chip Capacitor, 2-Leads, Body 1.60x0.80mm, IPC High Density"
  rect 0.75x0.85 smd: 1(-0.625,0) 2(0.625,0)
  body extent -0.85,-0.45 0.85,0.45, height 0.9
CONN16_S93515_WRE [mil]
  round 91 hole 71 paste-99999 mask+0: 1(0,0) 2(0,-110.24) 3(0,-220.48) 4(0,-330.72) 5(0,-440.96) 6(110.24,-440.96) 7(220.47,-440.96) 8(330.71,-440.96) 9(440.94,-440.96) 10(440.94,-330.72) 11(440.94,-220.48) 12(440.94,-110.24) 13(440.94,0) 14(330.71,0) 15(220.47,0) 16(110.24,0)
  silkscreen extent -68,-10 -65,10, body extent -28,-463 471,25, height 591
DVG0010A-MFG [mm]
  rect 1.65x4.41 smd paste+0 mask+0: 1(-4.875,2.54) 2(-4.875,-2.54)
  rect 1.65x0.6 smd paste+0 mask+0: 3(4.875,-4.445) 4(4.875,-3.175) 5(4.875,-1.905) 6(4.875,-0.635) 7(4.875,0.635) 8(4.875,1.905) 9(4.875,3.175) 10(4.875,4.445)
  silkscreen extent -6.37,-5.25 3.67,5.25, body extent -5.29,-5.15 5.04,5.15, height 2.59
EPSON-FC-135_V [mm] "SMD, 2-Leads, Body 3.2x1.5mm"
  rrect20% 1x1.8 smd: 1(-1.25,0) 2(1.25,0)
  silkscreen extent -0.35,-0.75 0.35,0.75, body extent -1.6,-0.75 1.6,0.75, height 0.9
FP-8-1437565-1-MFG [mm]
  rect 1.7x1 smd paste+0 mask+0: 1(-3.15,1.9) 2(3.15,1.9) 3(-3.15,-1.9) 4(3.15,-1.9)
  silkscreen extent -4.67,-2.6 2.55,2.6, body extent -3.3,-2.5 3.3,2.5, height 1.7
FP-1210-L_3_3_0_4-W_2_5_0-IPC_A [mm]
  rect 1.703x2.904 smd paste+0 mask+0: 1(-1.55,0) 2(1.55,0)
  silkscreen extent -0.4,-1.45 0.4,1.45, body extent -2.9,-1.95 2.9,1.95, height 0.25
FP-ABM3C-MFG [mm]
  rect 1.6x1.3 smd paste+0 mask+0: 1(-1.9,-1.15) 2(1.9,-1.15) 3(1.9,1.15) 4(-1.9,1.15)
  silkscreen extent -2.58,-2.48 2.58,1.68, body extent -2.5,-1.6 2.5,1.6, height 1.3
FP-AC0603-MFG [mm]
  rect 0.9x0.8 smd paste+0 mask+0: 1(-0.85,0) 2(0.85,0)
  silkscreen extent -0.85,-0.82 0.85,0.82, body extent -1.4,-0.55 1.4,0.55, height 0.25
FP-CC0603-DA-MFG [mm]
  rect 0.8x0.9 smd paste+0 mask+0: 1(-0.75,0) 2(0.75,0)
  silkscreen extent -0.85,-0.85 0.85,0.85, body extent -0.8,-0.4 0.8,0.4, height 0.9
FP-CGA3E-0_3-0_1-MFG [mm]
  rect 0.7x0.7 smd paste+0 mask+0: 1(-0.7,0) 2(0.7,0)
  silkscreen extent -0.95,-0.72 0.95,0.72, body extent -1.15,-0.65 1.15,0.65, height 0.25
FP-CL10-IPC_C [mm]
  rect 0.758x0.812 smd paste+0 mask+0: 1(-0.627,0) 2(0.627,0)
  silkscreen extent -1.01,-0.85 1.01,0.85, body extent -0.8,-0.4 0.8,0.4, height 0.9
FP-CL830-IPC_C [mm]
  rect 0.515x0.472 smd paste+0 mask+0: 1(-0.379,0) 2(0.379,0)
  silkscreen extent -0.64,-0.67 0.64,0.67, body extent -0.74,-0.38 0.74,0.38, height 0.25
FP-CRCW0603-e3-MFG [mm]
  rect 0.75x1 smd paste+0 mask+0: 1(-0.75,0) 2(0.75,0)
  silkscreen extent -0.8,-0.9 0.8,0.9, body extent -1.22,-0.6 1.22,0.6, height 0.25
FP-CRGCQ0603-IPC_C [mm]
  rect 0.758x0.812 smd paste+0 mask+0: 1(-0.627,0) 2(0.627,0)
  silkscreen extent -1.01,-0.85 1.01,0.85, body extent -0.8,-0.4 0.8,0.4, height 0.55
FP-DYF0002A-MFG [mm]
  rrect20% 0.9x0.5 smd paste+0 mask+0: 1(-1.3,0) 2(1.3,0)
  silkscreen extent -1.55,-0.7 0.9,0.93, body extent -1.33,-0.65 1.33,0.65, height 1
FP-GRM32-MFG [mm]
  rect 1.1x2.05 smd paste+0 mask+0: 1(-1.65,0) 2(1.65,0)
  silkscreen extent -0.72,-1.35 0.72,1.35, body extent -2.3,-1.45 2.3,1.45, height 0.25
FP-GRM155-0_05-MFG [mm]
  rect 0.4x0.5 smd paste+0 mask+0: 1(-0.4,0) 2(0.4,0)
  silkscreen extent -0.5,-0.65 0.5,0.65, body extent -0.5,-0.25 0.5,0.25, height 0.55
FP-GRM188-0_15-MFG [mm]
  rect 0.75x0.9 smd paste+0 mask+0: 1(-0.775,0) 2(0.775,0)
  silkscreen extent -0.8,-0.8 0.8,0.8, body extent -0.8,-0.4 0.8,0.4, height 0.95
FP-LTST-C191KGKT-MFG [mm]
  rect 0.8x0.8 smd paste+0 mask+0: 1(-0.75,0) 2(0.75,0)
  silkscreen extent -1.85,-0.8 0.8,0.8, body extent -0.8,-0.4 0.8,0.4, height 0.65
FP-RC0603-0_55-MFG [mm]
  rect 0.9x0.8 smd paste+0 mask+0: 1(-0.85,0) 2(0.85,0)
  silkscreen extent 0,-0.45 0,0.45, body extent -1.4,-0.55 1.4,0.55, height 0.25
FP-RMCF0603-IPC_A [mm]
  rect 1.206x1.058 smd paste+0 mask+0: 1(-0.801,0) 2(0.801,0)
  silkscreen extent -1.4,-0.93 1.4,0.93, body extent -1.9,-1.03 1.9,1.03, height 0.25
FP-RMCF0603-MFG [mm]
  rect 0.65x0.9 smd paste+0 mask+0: 1(-0.725,0) 2(0.725,0)
  silkscreen extent -0.85,-0.88 0.85,0.88, body extent -1.15,-0.58 1.15,0.58, height 0.25
FP-S3B-PH-K-S_LF_SN-MFG [mm]
  rect 1.2x1.2 hole 0.7 paste-2539.97 mask+0: 1(2,-2.45)
  round 1.2 hole 0.7 paste-2539.97 mask+0: 2(0,-2.45) 3(-2,-2.45)
  silkscreen extent -3.95,-3.8 3.95,3.8, body extent -3.95,-3.8 3.95,3.8, height 4.8
FP-S2761-46R-MFG [mm]
  rect 1.8x1 smd paste+0 mask+0: 1(0,0)
  silkscreen extent -0.85,-0.87 0.85,0.87, body extent -1,-0.6 1,0.6, height 0.25
FUSE_3555-2 [mm]
  round 5.59 hole 4.09: 1_1(-14.685,0) 1_2(-6.355,0) 2_1(6.345,0) 2_2(14.675,0)
  silkscreen extent -17.91,-3.3 17.91,2.25, body extent -18.03,-2.92 17.78,2.92, height 12.97
FUSE_3557-2 [mm]
  round 2.4 hole 1.6: 1_1(-6.735,1.7) 1_2(-6.735,-1.7) 2_1(6.735,1.7) 2_2(6.735,-1.7)
  silkscreen extent -9.9,-3.36 9.9,3.36, body extent -9.9,-3.36 9.9,3.36, height 7.37
IND_BOURNS_SRN6045 [mil]
  rect 79x236 smd paste+0 mask+0: 1(-85,0) 2(85,0)
  silkscreen extent -36,-127 36,127, body extent -118,-118 118,118, height 177
JST-S2B-PH-K-S_V [mm] "THD, 2-Leads, Body 7.6x5.9mm, Pitch 2mm"
  rect 1.2x1.2 hole 0.7: 1(-1,2.45)
  round 1.2 hole 0.7: 2(1,2.45)
  silkscreen extent -2.95,-3.8 2.95,4.35, body extent -2.95,-3.8 2.95,3.8, height 4.8
LQFP64_10X10_STM [mil]
  rect 52.78x11 smd paste+0 mask+0: 1(-223.39,147.68) 2(-223.39,127.99) 3(-223.39,108.3) 4(-223.39,88.61) 5(-223.39,68.91) 6(-223.39,49.23) 7(-223.39,29.53) 8(-223.39,9.85) 9(-223.39,-9.84) 10(-223.39,-29.53) 11(-223.39,-49.22) 12(-223.39,-68.91) 13(-223.39,-88.6) 14(-223.39,-108.3) 15(-223.39,-127.98) 16(-223.39,-147.68) 33(223.39,-147.68) 34(223.39,-127.98) 35(223.39,-108.3) 36(223.39,-88.6) 37(223.39,-68.91) 38(223.39,-49.22) 39(223.39,-29.53) 40(223.39,-9.84) 41(223.39,9.85) 42(223.39,29.53) 43(223.39,49.23) 44(223.39,68.91) 45(223.39,88.61) 46(223.39,108.3) 47(223.39,127.99) 48(223.39,147.68)
  rect 11x52.78 smd paste+0 mask+0: 17(-147.67,-223.39) 18(-127.98,-223.39) 19(-108.29,-223.39) 20(-88.6,-223.39) 21(-68.91,-223.39) 22(-49.22,-223.39) 23(-29.53,-223.39) 24(-9.84,-223.39) 25(9.85,-223.39) 26(29.54,-223.39) 27(49.23,-223.39) 28(68.91,-223.39) 29(88.61,-223.39) 30(108.3,-223.39) 31(127.99,-223.39) 32(147.68,-223.39) 49(147.68,223.39) 50(127.99,223.39) 51(108.3,223.39) 52(88.61,223.39) 53(68.91,223.39) 54(49.23,223.39) 55(29.54,223.39) 56(9.85,223.39) 57(-9.84,223.39) 58(-29.53,223.39) 59(-49.22,223.39) 60(-68.91,223.39) 61(-88.6,223.39) 62(-108.29,223.39) 63(-127.98,223.39) 64(-147.67,223.39)
  silkscreen extent -270,-270 270,270, body extent -236,-236 236,236, height 63
RESC1005X40X25LL05T10 [mm] "Chip Resistor, 2-Leads, Body 1.00x0.50mm, IPC High Density"
  rect 0.5x0.45 smd: 1(-0.375,0) 2(0.375,0)
  body extent -0.53,-0.27 0.53,0.28, height 0.4
RESC1608X55X25LL10T15 [mm] "Chip Resistor, 2-Leads, Body 1.60x0.80mm, IPC High Density"
  rect 0.6x0.8 smd: 1(-0.65,0) 2(0.65,0)
  body extent -0.85,-0.45 0.85,0.45, height 0.55
RESC1608X55X30LL15T15 [mm] "Chip Resistor, 2-Leads, Body 1.60x0.80mm, IPC High Density"
  rect 0.7x0.85 smd: 1(-0.625,0) 2(0.625,0)
  body extent -0.87,-0.48 0.87,0.48, height 0.55
SOD323_DIO [mm]
  rect 1.111x0.401 smd paste+0 mask+0: 1(-1.15,0) 2(1.15,0)
  silkscreen extent -1.03,-0.83 1.03,0.83, body extent -1.35,-0.7 1.35,0.7, height 0.81
SOIC8_D_TEX [mil]
  rect 57.5x22 smd paste+0 mask+0: 1(-107.25,75) 2(-107.25,25) 3(-107.25,-25) 4(-107.25,-75) 5(107.25,-75) 6(107.25,-25) 7(107.25,25) 8(107.25,75)
  silkscreen extent -84,-104 84,104, body extent -122,-99 122,99, height 69
SOT-23-6-DBV_TEX [mil]
  rect 38.5x22 smd paste+0 mask+0: 1(-53.75,37.4) 2(-53.75,0) 3(-53.75,-37.4) 4(53.75,-37.4) 5(53.75,0) 6(53.75,37.4)
  silkscreen extent -40,-65 40,65, body extent -59,-60 59,60, height 57
SOT_45-M3I_VIS [mil]
  rect 65x97 smd paste+0 mask+0: 1(-100,-297.5) 2(100,-297.5)
  rect 341x304 smd paste+0 mask+0: 3(0,94)
  silkscreen extent -206,-235 206,182, body extent -201,-332 201,225, height 71
TAYO-C1210-2_M [mm] "Chip Capacitor, 2-Leads, Body 3.50x2.70mm, IPC Low Density"
  rect 1.75x2.8 smd: 1(-1.425,0) 2(1.425,0)
  silkscreen extent -0.15,-1.3 0.15,1.3, body extent -1.75,-1.35 1.75,1.35, height 2.7
TO252_DIO [mil]
  rect 27x69 smd paste+0 mask+0: 1(-90,-207.93) 2(90,-207.93)
  rect 217x237 smd paste+0 mask+0: 3(0,64.5)
  silkscreen extent -135,-159 135,125, body extent -130,-228 130,169, height 91
USB-MICRO-B_V [mm] "USB, MICRO B, Body 7.491x4.695 mm, Pitch 0.65 mm"
  rect 0.4x1.35 smd: 1(-1.3,1.35) 2(-0.65,1.35) 3(0,1.35) 4(0.65,1.35) 5(1.3,1.35)
  round 1.45 hole 0.85: 6(-2.5,1.35) 7(2.5,1.35)
  rrect50% 0x0 hole 0.6 slot 1.3 at 90 deg: 8(-3.5,-1.35) 11(3.5,-1.35)
  rect 1.5x1.9 smd: 9(-1,-1.35) 10(1,-1.35)
  Top Layer circle w0.5: c-3.6,-1.8 r0.25
  Top Layer circle w0.5: c-3.6,-0.9 r0.25
  Top Layer circle w0.5: c3.6,-0.9 r0.25
  Top Layer circle w0.5: c3.6,-1.8 r0.25
  Top Layer region: -3.6,-1.8 -3.6,-0.9 -4.1,-0.9 -4.1,-1.8
  Top Layer region: -2.3,-2.3 -2.3,-0.4 -3.6,-0.4 -3.6,-2.3
  Top Layer region: 2.3,-0.4 2.3,-2.3 3.6,-2.3 3.6,-0.4
  Top Layer region: 3.6,-0.9 3.6,-1.8 4.1,-1.8 4.1,-0.9
  silkscreen extent -3.75,-3.5 3.75,2.7, body extent -4.1,-3.9 4.1,1.5, height 2.67
WL-SMCW_1206_150120xx75000 [mm] "SMD Mono-color Chip LED, body 3.2x1.6mm"
  rect 1.4x1.6 smd: 1(-1.5,0) 2(1.5,0)
  silkscreen extent -2.6,-0.75 -2.4,0.75, body extent -1.6,-0.8 1.6,0.8, height 0.68

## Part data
C1 C4: library part CMP-001-00163-1, "CGA Series 0603 0.1 uF 50 V ±10% Tolerance X8R Multilayer Ceramic Capacitor", Case/Package=0603, Max Operating Temperature=150°C, Min Operating Temperature=-55°C, Tolerance=10%, Voltage Rating=50V
C2 C3: library part CMP-001-00137-1, "Ceramic Capacitor, Multilayer, Ceramic, 50V, 10% +Tol, 10% -Tol, X7R, 15% TC, 4.7uF, Surface Mount, 1210", Capacitor Type=Ceramic, Case/Package=1210, Max Operating Temperature=125°C, Min Operating Temperature=-55°C
C5: library part CMP-001-00183-1, "50V 10uF X5R ±20% 1210 Multilayer Ceramic Capacitors MLCC - SMD/SMT ROHS", Case/Package=1210, Max Operating Temperature=85°C, Min Operating Temperature=-55°C, Tolerance=20%, Voltage Rating=50V
C6: library part CMP-001-00168-1, "25V 22uF X5R ±10% 1210 Multilayer Ceramic Capacitors MLCC - SMD/SMT ROHS", Case/Package=1210, Max Operating Temperature=85°C, Min Operating Temperature=-55°C, Tolerance=10%, Voltage Rating=25V
C7 C8 C9 C10 C12 C13 C14 C15 C16 C23: library part CMP-001-00174-1, "25V 100nF X7R 卤10% 0402 Multilayer Ceramic Capacitors MLCC - SMD/SMT ROHS", Case/Package=0402, Max Operating Temperature=125°C, Min Operating Temperature=-55°C, Tolerance=10%, Voltage Rating=25V
C11: library part CMP-001-00175-1, "25V 4.7uF X5R ±10% 0603 Multilayer Ceramic Capacitors MLCC - SMD/SMT ROHS", Case/Package=0603, Max Operating Temperature=85°C, Min Operating Temperature=-55°C, Tolerance=10%, Voltage Rating=25V
C17 C18: library part CMP-001-00180-1, "50V 18pF C0G ±5% 0402 Multilayer Ceramic Capacitors MLCC - SMD/SMT ROHS", Case/Package=0402, Max Operating Temperature=125°C, Min Operating Temperature=-55°C, Tolerance=5%, Voltage Rating=50V
C19 C20: library part CMP-001-00181-1, "50V 6pF C0G 0603 Multilayer Ceramic Capacitors MLCC - SMD/SMT ROHS", Case/Package=0603, Max Operating Temperature=125°C, Min Operating Temperature=-55°C, Voltage Rating=50V
C21: library part CMP-001-00172-1, "16V 1uF X7R ±10% 0603 Multilayer Ceramic Capacitors MLCC - SMD/SMT ROHS", Case/Package=0603, Max Operating Temperature=125°C, Min Operating Temperature=-55°C, Tolerance=10%, Voltage Rating=16V
C22: library part CMP-001-00176-1, "50V 10nF X7R ±10% 0603 Multilayer Ceramic Capacitors MLCC - SMD/SMT ROHS", Case/Package=0603, Max Operating Temperature=125°C, Min Operating Temperature=-55°C, Tolerance=10%, Voltage Rating=50V
C24 C25 C26 C27: library part CMP-001-00142-1, "Ceramic Capacitor, Multilayer, Ceramic, 50V, 5% +Tol, 5% -Tol, C0G, 30ppm/Cel TC, 0.001uF, Surface Mount, 0402", Capacitor Type=Ceramic, Case/Package=0402, Max Operating Temperature=125°C, Min Operating Temperature=-55°C
D1 D2 D3 D4 D5 D6 D7 D8 D9 D10 D11 D12 D13 D14 D15 D16 D17: library part CMP-007-00044-1, "Single Color LED, Bright Green, Water Clear, 2mm", Forward Current=30mA, Max Operating Temperature=85°C, Min Operating Temperature=-40°C
D18: library part CMP-004-00036-1, "LED yellow green 0603 wavelength 567.5~576.5nm light intensity 18~71mcd Front Mounting", Case/Package=0603, Forward Current=30mA, Forward Voltage=2.4V, Max Operating Temperature=85°C, Min Operating Temperature=-55°C
D19: library part CMP-004-00040-1, "5-V 60-A Unidirectional surge protection device 2-SOT -40 to 125", Case/Package=SOT, Max Operating Temperature=125°C, Min Operating Temperature=-40°C
F1 F5 F6 F7 F10 F11 F12 F13 F14 F15 F16 F17 F18 F19 F20: library part CMP-005-00014-1, "THM 2 in 1 Auto Blade Holder", Case/Package="Nonstandard Keystone"
F2 F3 F4 F8 F9: library part CMP-005-00015-2, "Auto Fuse Holder, 1 Fuse, Blade, Standard, THM, 50Amp, Hi-Temp Nylon, UL94V-0", Case/Package=None
J1 J2 J3 J6 J7 J8 J9 J10 J11 J12 J13 J14 J15 J16: library part CMP-002-00091-1, "Socket; DC supply; XT30; female; PIN: 2; on PCBs; THT; yellow; 15A", Case/Package=None
J4 J5: library part CMP-002-00096-1, "Socket, DC supply, XT90, female, PIN:2, on PCBs, THT", Case/Package=Package
J17 J18 J19 J20: library part CMP-083-000000-2, "Description", Manufacturer_Name="Wurth Electronics"
J21 J22: library part CMP-002-00094-1, "Board Connector, 3 Contact(s), 1 Row(s), Male, Right Angle, Solder Terminal", Max Current Rating=2A, Max Operating Temperature=85°C, Min Operating Temperature=-25°C, Voltage Rating=100V
J23: library part CMP-002-00081-1, "Telecom and Datacom Connector, 5 Contact(s), Female, Right Angle, Surface Mount Terminal, Detent, Receptacle", Max Operating Temperature=85°C, Min Operating Temperature=-30°C
J24 J25 J26 J27 J28 J29: library part CMP-002-00083-1, "Interconnection Device"
L1: library part CMP-006-00036-1, "Description", Manufacturer_Name="Bourns Electronics"
P1 P2: library part CMP-002-00030-2, "Male Header, Pitch 2 mm, 1 x 2 Position, Height 4.8 mm, Tail Length 3.4 mm, -25 to 85 degC, RoHS, Bulk", Case/Package=S2B-PH-K-S, Manufacturer="Japan Solderless Terminals", Max Operating Temperature=85°C, Min Operating Temperature=-25°C, Package Description="Male Header, Pitch 2 mm, 1 x 2 Position, Height 4.8 mm, Tail Length 3.4 mm"
P3: library part CMP-002-00093-1, "WR-PHD Straight Male, PCB Header, Through Hole, 1 Rows, 5 Contacts, 2.54mm Pitch", Max Operating Temperature=105°C, Min Operating Temperature=-40°C, Voltage Rating=250V
R1 R7 R8 R10 R30 R38 R39 R40 R41 R42 R43: library part CMP-009-00236-1, "Fixed Resistor, Metal Glaze/thick Film, 0.1W, 0ohm, Surface Mount, 0603", Case/Package=0603, Max Operating Temperature=155°C, Min Operating Temperature=-55°C, Power=100mW
R2: library part CMP-009-00292-1, "Res Thick Film 0603 130 Ohm 1% 0.1W(1/10W) ±100ppm/C Pad SMD T/R Automotive AEC-Q200", Case/Package=0603, Max Operating Temperature=155°C, Min Operating Temperature=-55°C, Tolerance=1%, Voltage Rating=75V
R3: library part CMP-009-00297-1, "CRCW FIXED RESISTOR 0603 (1608Metric) Chip Resistor ±1% ±100ppm/C 69.8kOhm 0.1W 1/10W", Case/Package=0603, Max Operating Temperature=155°C, Min Operating Temperature=-55°C, Tolerance=1%, Voltage Rating=75V
R4: library part CMP-009-00240-1, "Fixed Resistor, Metal Glaze/thick Film, 0.1W, 22100ohm, 75V, 1% +/-Tol, 100ppm/Cel, Surface Mount, 0603", Case/Package=0603, Max Operating Temperature=155°C, Min Operating Temperature=-55°C, Power=100mW, Tolerance=1%
R5 R6 R9 R28 R29 R31: library part CMP-009-00288-1, "100mW Thick Film Resistors ±100ppm/℃ ±1% 10kΩ 0603 Chip Resistor - Surface Mount ROHS", Case/Package=0603, Max Operating Temperature=155°C, Min Operating Temperature=-55°C, Tolerance=1%, Voltage Rating=75V
R11 R12 R13 R14 R15 R16 R17 R18 R19 R20 R21 R22 R23 R24 R25 R26: library part CMP-009-00296-1, "100Mw Thick Film Resistors 100Ppm/ 1% 2.2K 0603 Chip Resistor Surface Mount Rohs", Case/Package=0603, Max Operating Temperature=155°C, Min Operating Temperature=-55°C, Tolerance=1%, Voltage Rating=75V
R27: library part CMP-009-00289-1, "Res Thick Film 0603 220 Ohm 5% 0.1W(1/10W) ±100ppm/C Pad SMD Automotive T/R", Case/Package=0603, Max Operating Temperature=155°C, Min Operating Temperature=-55°C, Tolerance=5%, Voltage Rating=75V
R32 R33 R34 R36: library part CMP-009-00298-1, "Yageo RC0402FR-07150RL Resistor 0603 SMD 150 Ohm precision thick film", Case/Package=0402, Max Operating Temperature=155°C, Min Operating Temperature=-55°C, Tolerance=1%, Voltage Rating=50V
R35: library part CMP-009-00299-1, "Res Thick Film 0603 18K Ohm 1% 0.1W(1/10W) ±100ppm/C Pad SMD T/R Automotive AEC-Q200", Case/Package=0603, Max Operating Temperature=155°C, Min Operating Temperature=-55°C, Tolerance=1%, Voltage Rating=75V
R37: library part CMP-009-00293-1, "Res Thick Film 0603 2K Ohm 1% 1/10W ±100ppm/°C Molded SMD Punched Carrier T/R", Case/Package=0603, Max Operating Temperature=155°C, Min Operating Temperature=-55°C, Tolerance=1%, Voltage Rating=75V
SW1 SW2: library part CMP-011-00018-1, "Switch Tactile OFF (ON) SPST Round Button Gull Wing 0.05A 24VDC 2.55N SMD T/R", Case/Package=SMD/SMT, Max Current Rating=20mA, Max Operating Temperature=85°C, Min Operating Temperature=-35°C
U1: library part CMP-00030-00008-3, "4V to 36V, 1A, 80-ÂµA Iq synchronous SIMPLE SWITCHERÂ® power converter 6-SOT-23 -40 to 125", Manufacturer_Name="Texas Instruments"
U2 U3 U4: library part CMP-081-000000-2, "Â±1300V reinforced isolation, 80ARMS 250kHz Hall-effect current sensor with AFR, reference and ALERT 10-SOIC -40 to 125", Manufacturer_Name="Texas Instruments"
U5 U6 U7 U10 U11 U12 U13 U14 U15 U16 U17 U18 U19 U20: library part CMP-004-00037-2, "Description", Manufacturer_Name="Diodes Inc"
U8 U9: library part CMP-079-000001-3, "40A, 45V,TRENCH SKY RECT.", Manufacturer_Name=Vishay, Manufacturer_Part_Number=V40DL45-M3/I
U21: library part CMP-031-00007-1, "Mainstream Arm Cortex-M4 MCU 170 MHz with 512 Kbytes of Flash memory, Math Accelerator, High Analog level integration", Manufacturer_Name=STMicroelectronics
U22: library part CMP-064-000000-2, "Automotive 3.3V CAN flexible-data-rate (FD) transceiver with shutdown and standby mode 8-SOIC -40 to 150", Manufacturer_Name="Texas Instruments", Manufacturer_Part_Number=PTCAN3404DRQ1
U23 U24: library part CMP-093-000000-4, "Description", Manufacturer_Name="Diodes Inc"
Y1: library part CMP-003-00033-1, "Crystal, Standard, 16 MHz, SMD, 5mm x 3.2mm x 1.3mm, 30 ppm, 18 pF, 30 ppm, ABM3C", Case/Package=SMD/SMT, Frequency=16MHz, Load Capacitance=18pF, Max Operating Temperature=85°C, Min Operating Temperature=-40°C
Y2: library part CMP-003-00029-1, "Crystal 32.768kHz 10ppm 7pF -40C +85C", Frequency=32.768kHz

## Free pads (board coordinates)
  round 5 hole 3: 2(4.5,4.5) 2(4.5,155.5) 2(181,4) 2(181,156)

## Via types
v1: diameter 0.6, hole 0.3, Top Layer to Bottom Layer, 1109 vias

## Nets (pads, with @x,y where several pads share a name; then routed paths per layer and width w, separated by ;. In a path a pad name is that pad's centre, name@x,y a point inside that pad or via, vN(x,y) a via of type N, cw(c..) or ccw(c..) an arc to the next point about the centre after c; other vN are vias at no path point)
3.3V: C5.2 C6.2 C7.2 C8.2 C9.2 C10.2 C11.2 C12.2 C13.2 C14.2 C15.2 C16.2 C21.2 C22.2 C23.2 J26.1 L1.1 P3.4 R2.1 R3.2 R5.2 R6.2 R9.2 R28.2 R40.1 R41.1 R43.1 SW1.3 SW1.4 U2.8 U3.8 U4.8 U21.1 U21.16 U21.28 U21.29 U21.32 U21.48 U21.64 U22.3 | length 503.8
  Top Layer w0.4: R5.2@73.85,104 85,104 ; U2.8@77.405,113.125 77.464,113.066 77.464,111.415 C7.2@77.5,111.379 79.093,111.379 79.121,111.35 ; R40.1@83.301,112 83.301,110.449 83.5,110.25 ; U4.8@86,70.5 C9.2@87.621,70.5 87.643,70.5 87.679,70.536 87.679,70.86 89.75,72.931 89.75,75 ; R43.1@88,75.051 88.051,75 89.75,75 ; 89.75,79.25 89.75,75 ; R9.2@97.5,67.35 97.5,79.25 ; R41.1@123.898,78 123.972,78.074 123.972,78.901 125.16,80.09 ; 124.5,80.75 125.16,80.09 ; C8.2@128,77.621 128,77.643 127.964,77.679 127.571,77.679 125.16,80.09 ; U3.8@128.095,75.875 C8.2@128.095,77.505 ; 130.75,87 131.65,86.1 R6.2@131.65,85 ; SW1.3@146.75,111.95 SW1.4@146.75,118.25 146.75,129.5 150,132.75 165.098,132.75 169.602,137.254 169.602,139.991 169.445,140.148 v1(169.445,140.202) 167.19,140.202 167.18,140.212 166.962,140.212 166.952,140.202 166.962,140.192 166.962,140.158 166.75,139.946 166.75,136.484 166.516,136.25 160.035,136.25 159.785,136.5 v1(153.25,136.5) ; R28.2@151.15,120.25 151.15,121.1 150.684,121.566 150.684,131.906 150.918,132.14 165.692,132.14 170.532,136.98 170.532,140.818 171.726,142.012 171.726,145.85 172.401,146.525 C5.2@172.926,146.525 ; v1(151.405,127.75) 151.75,128.095 151.75,131.266 151.984,131.5 166.25,131.5 171.282,136.532 171.282,140.259 ; v1(154.851,124) 161.25,124 172.5,135.25 172.5,140.343 ; R2.1@160.1,142 L1.1@164.385,142 ; L1.1@164.385,141.5 L1.1@164.926,142.041 ; P3.4@166.21,112 166.21,120.71 175,129.5 175,140.964 ; v1@167.123,140.427 L1.1@167.123,141.191 ; v1(168.25,125) 173.75,130.5 173.75,141.312 ; R3.2@174.25,152.5 178,152.5 178.75,151.75 178.75,146.5 178.5,146.25 176.476,146.25 C6.2@176.426,146.3
  Top Layer w0.5: 79.121,111.35 79.407,111.35 79.757,111
  Top Layer w0.6: 79.757,111 80.507,110.25 83.5,110.25 84.649,110.25 85,109.899 85,104 85,81.25 87,79.25 89.75,79.25 97.5,79.25 123,79.25 124.5,80.75 130.75,87 138.5,94.75 138.5,105.149 141.601,108.25 155.75,108.25 157.5,110 174.25,110 177,112.75 177,140.36
  Bottom Layer w0.2: C11.2@150.75,126.525 150.75,127.095 v1(151.405,127.75) ; C11.2@150.825,126.525 151.405,127.105 C12.2@152.5,127.105 ; C12.2@152.5,127.127 152.872,127.499 U21.1@154.076,127.499 ; C16.2@152.5,135.229 152.636,135.092 153.014,135.092 153.106,135.001 U21.16@154.076,135.001 ; C16.2@152.5,135.25 152.5,135.75 v1(153.25,136.5) ; v1(154.851,124) C13.2@155.871,124 155.871,124.918 155.999,125.045 U21.64@155.999,125.576 ; C23.2@161.25,138.5 161.25,139.05 161.625,139.425 161.625,139.675 C22.2@161.875,139.675 ; C23.2@161.271,138.5 161.5,138.271 U21.28@161.5,136.924 ; C22.2@161.9,139.675 C22.2@161.9,139.975 ; U21.29@162.001,136.924 C22.2@162.001,139.874 ; v1(163,140.5) 163,141.1 162.35,141.75 C21.2@161.75,141.75 ; U21.32@163.501,136.924 163.541,136.964 163.541,137.662 163.842,137.964 164.003,137.964 164.221,138.181 164.221,138.364 164.357,138.5 C15.2@164.379,138.5 165.75,138.5 166.337,139.087 166.337,139.587 v1(167,140.25) ; v1(164.25,140.25) 163.874,139.874 C22.2@162.001,139.874 ; U21.48@165.424,127.499 165.955,127.499 166.454,127 C14.2@167,127 167,126.25 v1(168.25,125) ; C10.2@168.5,139.129 C10.2@168.5,139.15 ; v1(169.445,140.202) 169.401,140.158 168.845,140.158 168.5,139.813 C10.2@168.5,139.15 ; U22.3@170.552,139.54 168.911,139.54 168.658,139.286 168.636,139.286 C10.2@168.5,139.15 ; C21.2@161.75,141.75 161.75,141.7 C21.2@161.875,141.575 ; C21.2@161.75,141.75 161.875,141.625 C21.2@161.875,141.575 ; C21.2@161.875,141.575 C22.2@161.875,140 C22.2@161.9,139.975 ; C22.2@161.9,139.975 C22.2@162.001,139.874
3V3_CB: C1.1 U1.1 | length 1.7
  Top Layer w0.4: U1.1@169.041,148.75 169.097,148.75 169.176,148.67 C1.1@169.176,147.15
3V3_EN: R1.2 U1.4 | length 12.7
  Top Layer w0.3: R1.2@157.5,146 v1(159.25,146) ; v1(166.25,151.75) 166.25,150.71 U1.4@166.311,150.65
  Bottom Layer w0.3: v1(159.25,146) 161.25,146 166.25,151 v1(166.25,151.75)
3V3_FB: R3.1 R4.1 U1.3 | length 5.3
  Top Layer w0.4: U1.3@169.041,150.65 169.041,152.041 169.5,152.5 171.001,152.5 R4.1@171.026,152.475 171.038,152.487 172.737,152.487 R3.1@172.75,152.5
3V3_SW: C1.2 L1.2 U1.6
5V_UART_RX: P2.1 U21.55 | length 28.2
  Bottom Layer w0.2: U21.55@160.5,125.576 160.5,124.053 172.803,111.75 P2.1@182.05,111.75
5V_UART_TX: P2.2 U21.54 | length 26.8
  Bottom Layer w0.2: U21.54@161,125.576 161,124.118 171.369,113.75 P2.2@182.05,113.75
18V_12V_UART_RX: P1.1 U21.53 | length 24.2
  Bottom Layer w0.2: U21.53@161.5,125.576 161.5,124.184 166.934,118.75 P1.1@182.05,118.75
18V_12V_UART_TX: P1.2 U21.52 | length 23.4
  Bottom Layer w0.2: U21.52@162.001,125.576 162.001,124.249 166.25,120 181.106,120 181.856,120.75 P1.2@182.05,120.75
24V: F1.1_1 F1.1_2 F2.1_1 F2.1_2 F3.1_1 F3.1_2 F4.1_1 F4.1_2 J17.1 J17.2 J17.3 J17.4 J17.5 J17.6 J17.7 J17.8 J17.9 J17.10 J17.11 J17.12 J17.13 J17.14 J17.15 J17.16 J19.1 J19.2 J19.3 J19.4 J19.5 J19.6 J19.7 J19.8 J19.9 J19.10 J19.11 J19.12 J19.13 J19.14 J19.15 J19.16 J24.1 R35.2 | length 4
  Top Layer w0.3: 141.35,133.5 R35.2@145.4,133.5
  other v1: 106,84 109,84 112.25,84 122,84 88,87 91,87 94,87 97,87 100,87 103,87 106,87 109,87 112,87 122,87 125,87 88,90 91,90 94,90 97,90 100,90 103,90 106,90 109,90 112,90 122,90 125,90 128,90 88,93 91,93 94,93 97,93 100,93 103,93 106,93 109,93 112,93 122,93 125,93 128,93 131,93 88,96 91,96 94,96 97,96 100,96 103,96 106,96 109,96 112,96 122,96 125,96 128,96 131,96 94,99 97,99 100,99 103,99 106,99 109,99 112,99 122,99 125,99 128,99 131,99 94,102 97,102 100,102 103,102 106,102 109,102 112,102 115,102 118,102 121,102 124,102 127,102 130,102 94,105 97,105 100,105 103,105 106,105 109,105 112,105 115,105 118,105 121,105 124,105 127,105 130,105 94,108 97,108 100,108 103,108 106,108 109,108 112,108 115,108 118,108 121,108 124,108 127,108 130,108 94,111 97,111 100,111 103,111 106,111 109,111 112,111 115,111 118,111 121,111 124,111 127,111 130,111 133,111 137.25,113.25 97,113.75 100,113.75 103,113.75 106,113.75 109,113.75 112,113.75 114.75,113.75 117.5,113.75 121,113.75 124,113.75 127,113.75 130,113.75 133,113.75 97.75,115.75 113,116 115.75,116 118.25,116 134,116 137.25,116 140,116 97.75,118.5 113,118.75 115.75,118.75 118.25,118.75 134,118.75 137.25,118.75 140,118.75 97.75,121.5 134,121.5 137.25,121.5 140,121.5 113,121.65 115.75,121.75 118.25,121.75 97.75,124.25 113,124.5 115.75,124.5 118.25,124.5 134,124.5 137.25,124.5 140,124.5 97.75,127 134,127.25 137.25,127.25 140,127.25 113,127.5 115.75,127.5 118.25,127.5 98.503,129.244 101.503,129.244 104.503,129.244 107.503,129.244 110.503,129.244 113.25,129.25 116.75,129.25 119.503,129.244 122.503,129.244 125.503,129.244 128.503,129.244 131.503,129.244 137.25,129.75 140,129.75 99.972,130.8 102.972,130.8 105.972,130.8 108.972,130.8 111.722,130.8 114.472,130.8 117.972,130.8 120.972,130.8 123.972,130.8 126.972,130.8 129.972,130.8 137.25,132.5 140,132.5 137.25,135.75 140,135.75 137.25,138.5 140,138.5 137.25,141.25 140,141.25 137.25,143.75 140,143.75 137.25,146.25 140,146.25 137.25,148.75 140,148.75 137.75,157 139.75,157
24V_ARM1: F8.2_1 F8.2_2 J4.P R14.2 U8.3 | length 15.7
  Top Layer w0.3: F8.2_1@43.305,133 50,133 50.6,133.6 R14.2@50.6,141.75
  other v1: 41,123 45,123 12.697,123.157 17.197,123.157 21.197,123.157 25.197,123.157 29.197,123.157 33.197,123.157 37.197,123.157 11,125 15,125 19.5,125 23.5,125 27.5,125 31.5,125 35.5,125 39.5,125 43,125 46.975,125 17.5,127 21.5,127 25.5,127 33.5,127 37.5,127 41.5,127 45,127 29.197,127.157 31.5,129 35.5,129 39.5,129 43.5,129 47,129
24V_ARM2: F9.2_1 F9.2_2 J5.P R15.2 U9.3 | length 15.4
  Top Layer w0.3: F9.2_1@43.305,102 50,102 50.6,102.6 R15.2@50.6,110.5
  other v1: 41,92 45,92 12.697,92.157 17.197,92.157 21.197,92.157 25.197,92.157 29.197,92.157 33.197,92.157 37.197,92.157 11,94 15,94 19.5,94 23.5,94 27.5,94 31.5,94 35.5,94 39.5,94 43,94 46.975,94 17.5,96 21.5,96 25.5,96 33.5,96 37.5,96 41.5,96 45,96 29.197,96.157 31.5,98 35.5,98 39.5,98 43.5,98 47,98
24V_ARM_F: F2.2_1 F2.2_2 U2.1
  other v1: 83,119 86,119 95,119 83,122 85.75,122 95,122 77,125 80,125 83,125 86,125 95,125 77,128 80,128 83,128 86,128 95,128 77,131 80,131 83,131 86,131 95,131 77,134 80,134 83,134 86,134 89,134 92,134 95,134 80,137 83,137 86,137 89,137 92,137 95,137
24V_ARM_S: F8.1_1 F8.1_2 F9.1_1 F9.1_2 J28.1 U2.2
  other v1: 55,93 60,93 65,93 55,96 60,96 65,96 55,108 60,108 65,108 56,112 60,112 65,112 55,115 60,115 65,115 55,118 60,118 65,118 55,121 60,121 65,121 69,121 55,124 60,124 65,124 69,124 71,126 74,126 55,127 60,127 65,127 68,128 70,130 69,133 55,138 60,138 65,138
24V_BUCK: C2.1 C3.1 C4.2 F1.2_1 F1.2_2 R1.1 U1.5
24V_CHASSIS_F: F3.2_1 F3.2_2 U3.1
  other v1: 108,57 111,57 114,57 117,57 120,57 123,57 126,58 129,58 108,60 111,60 114,60 117,60 120,60 123,60 126,61 129,61 108,63 111,63 114,63 117,63 120,63 123,63 126,64 129,64 108,66 111,66 114,66 123,66 108,69 111,69 114,69 123,69 108,72 111,72 114,72 122,72 108,75 111,75 114,75 121.927,75.007 121.853,77.553 108,78 111,78 114,78
24V_CHASSIS_S: F5.1_1 F5.1_2 F6.1_1 F6.1_2 F7.1_1 F7.1_2 F10.1_1 F10.1_2 F11.1_1 F11.1_2 F12.1_1 F12.1_2 J27.1 U3.2
  other v1: 146.25,17.25 150,17.25 146.25,26.5 150.25,26.5 146,30 150,30 140,35 145,35 150,35 135,40 140,40 145,40 130,45 135,45 140,45 145,45 135,50 140,50 145,50 150,50 133,55 139,55 145,55 150,55 135,60 140,60 145,60 132,62 136,65 140,65 145,65 150,65 145,70 150,70 145,75 150,75 145,80 145,85 150,85 145,90 150,90 145,95 145,100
